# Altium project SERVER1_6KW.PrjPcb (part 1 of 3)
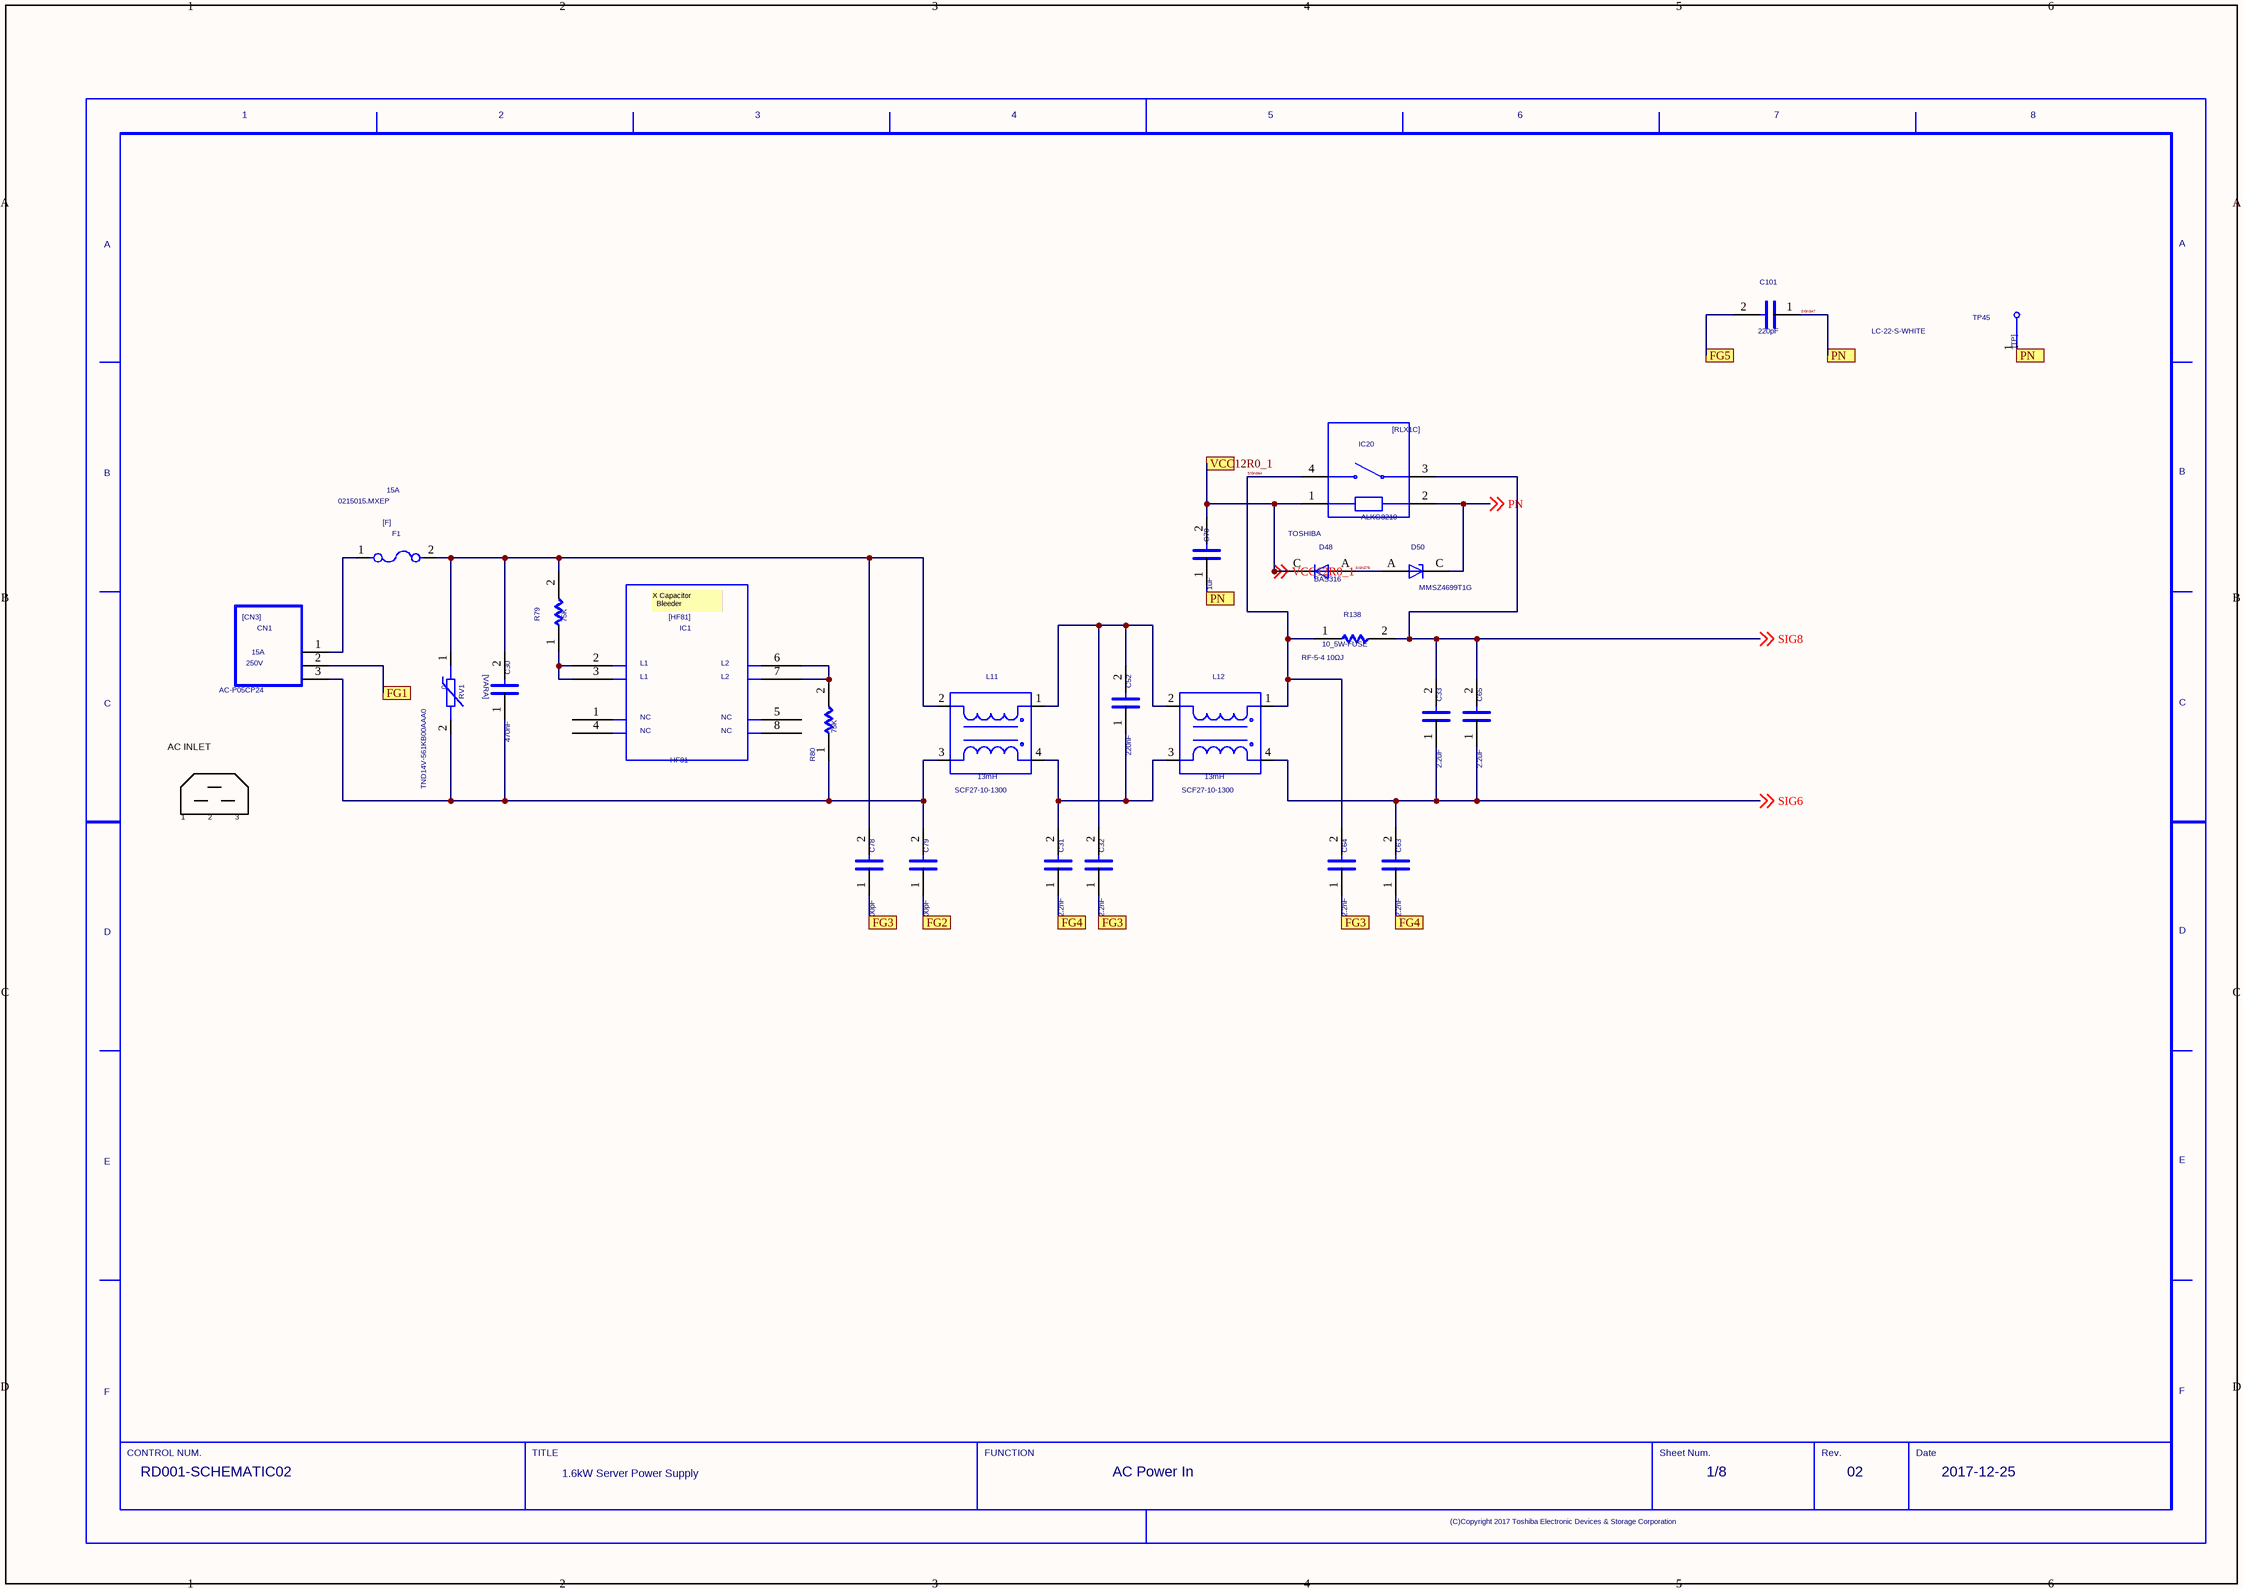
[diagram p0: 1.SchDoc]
8 sheets, 447 parts. Net scope: flat (ports and power ports of the same name join across sheets).
Sheets:
  1.SchDoc
  2.SchDoc
  3.SchDoc
  4.SchDoc
  5.SchDoc
  6.SchDoc
  7.SchDoc
  8.SchDoc

## Sheet 1.SchDoc
size 420 x 297 mm

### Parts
(Parts that share a designator on the sheet are numbered #1, #2 ... from top to bottom, then left to right.)
C30  VAL1: 470nF  (hidden comment: C)
C31  VAL1: 2.2nF  (hidden comment: C)
C32  VAL1: 2.2nF  (hidden comment: C)
C33  VAL1: 2.2uF  (hidden comment: C)
C52  VAL1: 220nF  (hidden comment: C)
C63  VAL1: 2.2nF  (hidden comment: C)
C64  VAL1: 2.2nF  (hidden comment: C)
C65  VAL1: 2.2uF  (hidden comment: C)
C70  VAL1: 1uF  (hidden comment: C)
C78  VAL1: 100pF  (hidden comment: C)
C79  VAL1: 100pF  (hidden comment: C)
C101  VAL1: 220pF  (hidden comment: C)
CN1  VAL2: 250V  VAL1: 15A  VAL3: AC-P05CP24  (hidden comment: CN3)
D48  USERCOMPTEXT3: TOSHIBA  VAL3: BAS316  (hidden comment: D)
D50  VAL3: MMSZ4699T1G  (hidden comment: ZD)
F1  VAL1: 15A  VAL3: 0215015.MXEP  (hidden comment: F)
IC1  VAL3: HF81  (hidden comment: L81)
IC20  VAL3: ALKG8210  (hidden comment: RLX1C)
L11  VAL3: SCF27-10-1300  VAL1: 13mH  (hidden comment: HM-DLWHN6702)
L12  VAL3: SCF27-10-1300  VAL1: 13mH  (hidden comment: HM-DLWHN6702)
R79  VAL1: 75K  (hidden comment: R)
R80  VAL1: 75K  (hidden comment: R)
R138  VAL3: RF-5-4 10ΩJ  VAL1: 10_5W-FUSE  (hidden comment: R)
RV1  VAL3: TND14V-561KB00AAA0  (hidden comment: VARA)
TP45  VAL3: LC-22-S-WHITE  (hidden comment: TP)
U?#1  DATE: 2017-12-25  TITLE: 1.6kW Server Power Supply  REVISION: 02  SHEETNUMBER: 1/8  DRAWINGNUMBER: RD001-SCHEMATIC02  FUNCTION: AC Power In  (hidden comment: WAKU_DEF100)

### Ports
FG1, FG2, FG3, FG4, FG5, PN, VCC12R0_1

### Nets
SIG1: C30.2 C78.2 F1.2 L11.2 R79.2 RV1.1
SIG2: C30.1 C79.2 CN1.3 L11.3 R80.1 RV1.2
SIG6: C33.1 C63.2 C65.1 L12.4 ; off-sheet SIG6
SIG8: C33.2 C65.2 IC20.3 R138.2 ; off-sheet SIG8
SIG9: IC1.2 IC1.3 R79.1
SIG10: IC1.6 IC1.7 R80.2
SIG193: CN1.1 F1.1
SIG199: C32.2 C52.2 L11.1 L12.2
SIG200: C31.2 C52.1 L11.4 L12.3
SIGN275: D48.A D50.A
SIGN347: C70.1 C101.1 D50.C IC20.2 TP45.1 ; off-sheet PN, port PN  [also labelled PN]
SIGN364: C64.2 IC20.4 L12.1 R138.1
VCC12R0_1: C70.2 D48.C IC20.1 ; off-sheet VCC12R0_1, port VCC12R0_1
NetC31_1: C31.1 C63.1 ; port FG4
NetC32_1: C32.1 C64.1 C78.1 ; port FG3
NetC79_1: C79.1 ; port FG2
NetC101_2: C101.2 ; port FG5
NetCN1_2: CN1.2 ; port FG1

Not connected (* = marked no-connect by the designer): IC1 1 4 5 8

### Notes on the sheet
- AC INLET
- 1
- 2
- 3

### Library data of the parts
C30 = C: OriginalSymbolOrigin: (2540,7620); COMP: PRT_19; MAKER: OKAYA; VAL2: 275V,±10%; VAL3: LE474-M; RATEDVOLTAGE: 100; MAXGCOUNT: 1; SIZECODESMD: 3225; NOMINALCAPACITA: 470n; CAPACITANCETOLE: K; ADSMODELNAME: s_GRM32MR72A474KA01L
C31 = C: OriginalSymbolOrigin: (2540,7620); PMPRODUCTSTYPEG: ES; COMP: PRT_13; VAL2: 250V,±20%; MAKER: MURATA; CHIPSIZE: リードピッチ7.5mm品希望; VAL3: DE2E3KY222MN3AM02F; RATEDVOLTAGE: 250; MAXGCOUNT: 1; TEMPCHARACTERI2: E; OUMEMAKER: NAE パナソニックエレクトロニックデバイス; QUADMODEL: CON_2.2N; FNLEADFREETHET1GT2GMCTH1: N_N_N; OUMECLASSIFICATION: セラミックコンデンサ; SIZECODESMD: DIP; NOMINALCAPACITA: 2.2n; OUMEMAKERKATAMEI: ECKNTS222ME; CAPACITANCETOLE: M; CDMASTERCADCELG: DC0284; ADSMODELNAME: s_ECKNTS222ME
C32 = C: SQ_PART_MODEL: CON_2.2N; OriginalSymbolOrigin: (2540,7620); PMPRODUCTSTYPEG: ES; COMP: PRT_13; VAL2: 250V,±20%; MAKER: MURATA; CHIPSIZE: リードピッチ7.5mm品希望; VAL3: DE2E3KY222MN3AM02F; RATEDVOLTAGE: 250; MAXGCOUNT: 1; TEMPCHARACTERI2: E; OUMEMAKER: NAE パナソニックエレクトロニックデバイス; FNLEADFREETHET1GT2GMCTH1: N_N_N; OUMECLASSIFICATION: セラミックコンデンサ; SIZECODESMD: DIP; NOMINALCAPACITA: 2.2n; ADSCNVFLAG: ON; OUMEMAKERKATAMEI: ECKNTS222ME; CAPACITANCETOLE: M; CDMASTERCADCELG: DC0284; ADSMODELNAME: s_ECKNTS222ME
C33 = C: OriginalSymbolOrigin: (2540,7620); FNLEADFREETHET1GT2GMCTH1: 9_N_N; CDMASTERCADCELG: DC0511; OUMEMAKER: CHM 日本ケミコン; OUMEMAKERKATAMEI: TACB2E225K; OUMECLASSIFICATION: フィルャRンデンサ; QUADMODEL: CON_2.2U; COMP: PRT_18; MAKER: Wurth; VAL2: 275V,±10%; VAL3: 890324026034CS; RATEDVOLTAGE: 250; MAXGCOUNT: 1; SIZECODESMD: DIP; NOMINALCAPACITA: 2.2u; CAPACITANCETOLE: K
C52 = C: OriginalSymbolOrigin: (2540,7620); FNLEADFREETHET1GT2GMCTH1: N_N_N; OUMEMAKER: NIS ニッセイ電機; OUMEMAKERKATAMEI: R40KI322000**M; OUMECLASSIFICATION: フィルャRンデンサ; QUADMODEL: CON_220N; COMP: PRT_17; MAKER: OKAYA; VAL2: 275V,±10%; VAL3: LE224-M; RATEDVOLTAGE: 275; MAXGCOUNT: 1; SIZECODESMD: DIP; NOMINALCAPACITA: 220n; CAPACITANCETOLE: M
C63 C64 = C: OriginalSymbolOrigin: (2540,7620); PMPRODUCTSTYPEG: PC1; COMP: PRT_13; VAL2: 250V,±20%; MAKER: MURATA; CHIPSIZE: リードピッチ7.5mm品希望; VAL3: DE2E3KY222MN3AM02F; TEMPCHARACTERI2: E; RATEDVOLTAGE: 250; MAXGCOUNT: 1; OUMEMAKER: MRT 村田製作所; QUADMODEL: CON_2.2N; FNLEADFREETHET1GT2GMCTH1: N_N_N; OUMECLASSIFICATION: セラミックコンデンサ; SIZECODESMD: DIP; NOMINALCAPACITA: 2.2n; CAPACITANCETOLE: M; CDMASTERCADCELG: SIK0018; ADSMODELNAME: s_DE2E3KY222MN3AM02F
C65 = C: OriginalSymbolOrigin: (2540,7620); FNLEADFREETHET1GT2GMCTH1: 9_N_N; CDMASTERCADCELG: DC0511; OUMEMAKER: CHM 日本ケミコン; OUMEMAKERKATAMEI: TACB2E225K; OUMECLASSIFICATION: フィルャRンデンサ; QUADMODEL: CON_2.2U; COMP: PRT_18; MAKER: Wurth; VAL2: 270V,±10%; VAL3: 890324026034CS; RATEDVOLTAGE: 250; MAXGCOUNT: 1; SIZECODESMD: DIP; NOMINALCAPACITA: 2.2u; CAPACITANCETOLE: K
C70 = C: OriginalSymbolOrigin: (2540,7620); COMP: PRT_52; VAL3: C1005X5R1E105M050BC; MAKER: TDK; CHIPSIZE: 1005; VAL2: 25V,±20%; TEMPCHARACTERI2: B; PMPRODUCTSTYPEG: HD1; RATEDVOLTAGE: 25; MAXGCOUNT: 1; OUMEMAKER: MRT 村田製作所; QUADMODEL: CON_1U; FNLEADFREETHET1GT2GMCTH1: 3_0_N; OUMECLASSIFICATION: セラミックコンデンサ; NOMINALCAPACITA: 1u; OUMEMAKERKATAMEI: GRM155B31E105KA12D; CAPACITANCETOLE: K; CDMASTERCADCELG: KC0005; ADSMODELNAME: s_GRM155B31E105KA12D
C78 C79 = C: OriginalSymbolOrigin: (2540,7620); FNLEADFREETHET1GT2GMCTH1: N_N_N; CDMASTERCADCELG: RDK0051; OUMEMAKER: MRT 村田製作所; OUMEMAKERKATAMEI: DE1B3KX101KA4BL01; OUMECLASSIFICATION: セラミックコンデンサ; QUADMODEL: CON_100P; COMP: PRT_29; VAL2: 250V,±10%; MAKER: MURATA; VAL3: DE2B3KY101KA3BM02F; CHIPSIZE: リードピッチ7.5mm品希望; RATEDVOLTAGE: 250; MAXGCOUNT: 1; TEMPCHARACTERI2: B; NOMINALCAPACITA: 100p; CAPACITANCETOLE: K; ADSMODELNAME: s_DE1B3KX101KA4BL01
C101 = C: OriginalSymbolOrigin: (2540,7620); FNLEADFREETHET1GT2GMCTH1: 9_1_N; CDMASTERCADCELG: RD0002; OUMEMAKER: MRT 村田製作所; OUMEMAKERKATAMEI: DEBB33A221KC1B; OUMECLASSIFICATION: セラミックコンデンサ; QUADMODEL: CON_220P; VAL2: 250V,±10%; COMP: PRT_50; MAKER: MURATA; VAL3: DE2B3KY221KA3BM02F; TEMPCHARACTERI2: B; RATEDVOLTAGE: 1K; MAXGCOUNT: 1; SIZECODESMD: DIP; NOMINALCAPACITA: 220p; CAPACITANCETOLE: K; ADSMODELNAME: s_DEBB33A221KC1B
CN1 = CN3: OriginalSymbolOrigin: (2540,17780); MAKER: ECHO ELECTRIC; COMP: PRT_61
D48 = D: SAVEAREA0: -225,-91,12804,7836; SAVECOUNT: 3; TIME: 14:49:55; UPDATEUSER: 19870035; UPDATETIME: 14:20:16; OriginalSymbolOrigin: (5080,5080); COMP: PRT_26; FORWARDVOLTAGEM: 0; MAXGCOUNT: 1; OUMEMAKER: IFO インフィニオンテクノロジーズ; MOUNTINGFORMSMD: SMD; FNLEADFREETHET1GT2GMCTH1: N_N_N; OUMECLASSIFICATION: その他ダイオード; OUMEMAKERKATAMEI: BAS16-02W; CDMASTERCADCELG: D8101D; ADSMODELNAME: s_BAS16_02W
D50 = ZD: OUMEPARTTYPE: D; SAVEAREA0: -4630,-153,17114,13055; TIME: 14:49:55; UPDATEUSER: fukuda-y; UPDATETIME: 08:18:42; SAVECOUNT: 6; OriginalSymbolOrigin: (5080,5080); COMP: PRT_47; MAKER: ON Semiconductor; FORWARDVOLTAGEM: 0; MAXGCOUNT: 1; OUMEMAKER: ONS オンセミコンダクター; MOUNTINGFORMSMD: SMD; FNLEADFREETHET1GT2GMCTH1: N_N_N; ZENERVOLTAGEMIN: 2.28; OUMECLASSIFICATION: 定電圧ダイオード; OUMEMAKERKATAMEI: MMSZ4681T1G; CDMASTERCADCELG: MMK0127; ZENERVOLTAGEMAX: 2.52; ADSMODELNAME: s_MMSZ4681T1G
F1 = F: OriginalSymbolOrigin: (2540,5080); COMP: PRT_21; MAKER: Littelfuse; RATEDVOLTAGE: 0; MAXGCOUNT: 1; MOUNTINGFORMSMD: SMD
IC1 = L81: SAVEAREA0: -12429,-3512,55842,41521; TIME: 18:31:00; UPDATEUSER: cae; UPDATETIME: 11:10:50; SAVECOUNT: 13; OriginalSymbolOrigin: (7620,35560); MAKER: MPS; COMP: PRT_45
IC20 = RLX1C: SAVECOUNT: 9; SAVEAREA0: -15461,-296,40419,28727; OriginalSymbolOrigin: (5080,20320); COMP: PRT_1; MAKER: PANASONIC; UPDATETIME: 11:13:08; UPDATEUSER: cae; TIME: 14:49:55
L11 L12 = HM-DLWHN6702: DEVICENAME: DLW21HN670SQ2; SAVEAREA0: -21350,-26515,41553,39372; TIME: 11:39:40; UPDATEUSER: user1; UPDATETIME: 19:05:24; SAVECOUNT: 4; OriginalSymbolOrigin: (2540,12700); MAKER: NEC TOKIN; COMP: PRT_22
R79 R80 = R: OriginalSymbolOrigin: (5080,5080); POWERRATING: 250m; RESISTANCETOLER: F; NOMINALRESISTAN: 56K; FNLEADFREETHET1GT2GMCTH1: N_N_N; CDMASTERCADCELG: DR903A; OUMEMAKER: KOA コーア; OUMEMAKERKATAMEI: RK73H2ETE563F; OUMECLASSIFICATION: 表面実装用固定抵抗器; QUADMODEL: RES_56K; COMP: PRT_23; MAKER: PANASONIC; VAL3: ERJ-14NF7502U; CHIPSIZE: 3225; VAL2: 500mW,±1%; MAXGCOUNT: 1; MOUNTINGFORMSMD: SMD; ADSMODELNAME: s_RK73H2ETE563F
R138 = R: OriginalSymbolOrigin: (5080,5080); MAKER: TAKMAN; CHIPSIZE: 13x9xH25.5; COMP: PRT_33
RV1 = VARA: OUMEPARTTYPE: RV; SAVEAREA0: -9950,-8554,25168,13619; SAVECOUNT: 12; TIME: 09:56:50; UPDATEUSER: tomizawa-y; OriginalSymbolOrigin: (2540,5080); COMP: PRT_37; MAKER: NIPPON CHEMICON; VAL1: 560V; RATEDVOLTAGE: 0; MAXGCOUNT: 1; OUMEMAKER: TDK ＴＤＫ; MOUNTINGFORMSMD: SMD; FNLEADFREETHET1GT2GMCTH1: N_N_N; OUMECLASSIFICATION: バリスタ; OUMEMAKERKATAMEI: AVR-M1608C220KT6AB; CDMASTERCADCELG: KC0008
TP45 = TP: TIME: 16:12:21; UPDATEUSER: fukuda-y; UPDATETIME: 16:18:11; SAVECOUNT: 2; SAVEAREA0: -242,-92,12810,7836; OriginalSymbolOrigin: (0,7620); COMP: PRT_49; MAKER: MAC8
U?#1 = WAKU_DEF100: PLOTTIME: HH:MM; SAVEAREA0: -45080,-4508,463680,304612; TIME: 10:19:22; UPDATEUSER: f1043010; UPDATETIME: 13:49:58; SAVECOUNT: 3; OriginalSymbolOrigin: (10160,284480); PAGENUMBER: 2; DESIGNED: TOSHIBA

## Sheet 2.SchDoc
size 420 x 297 mm
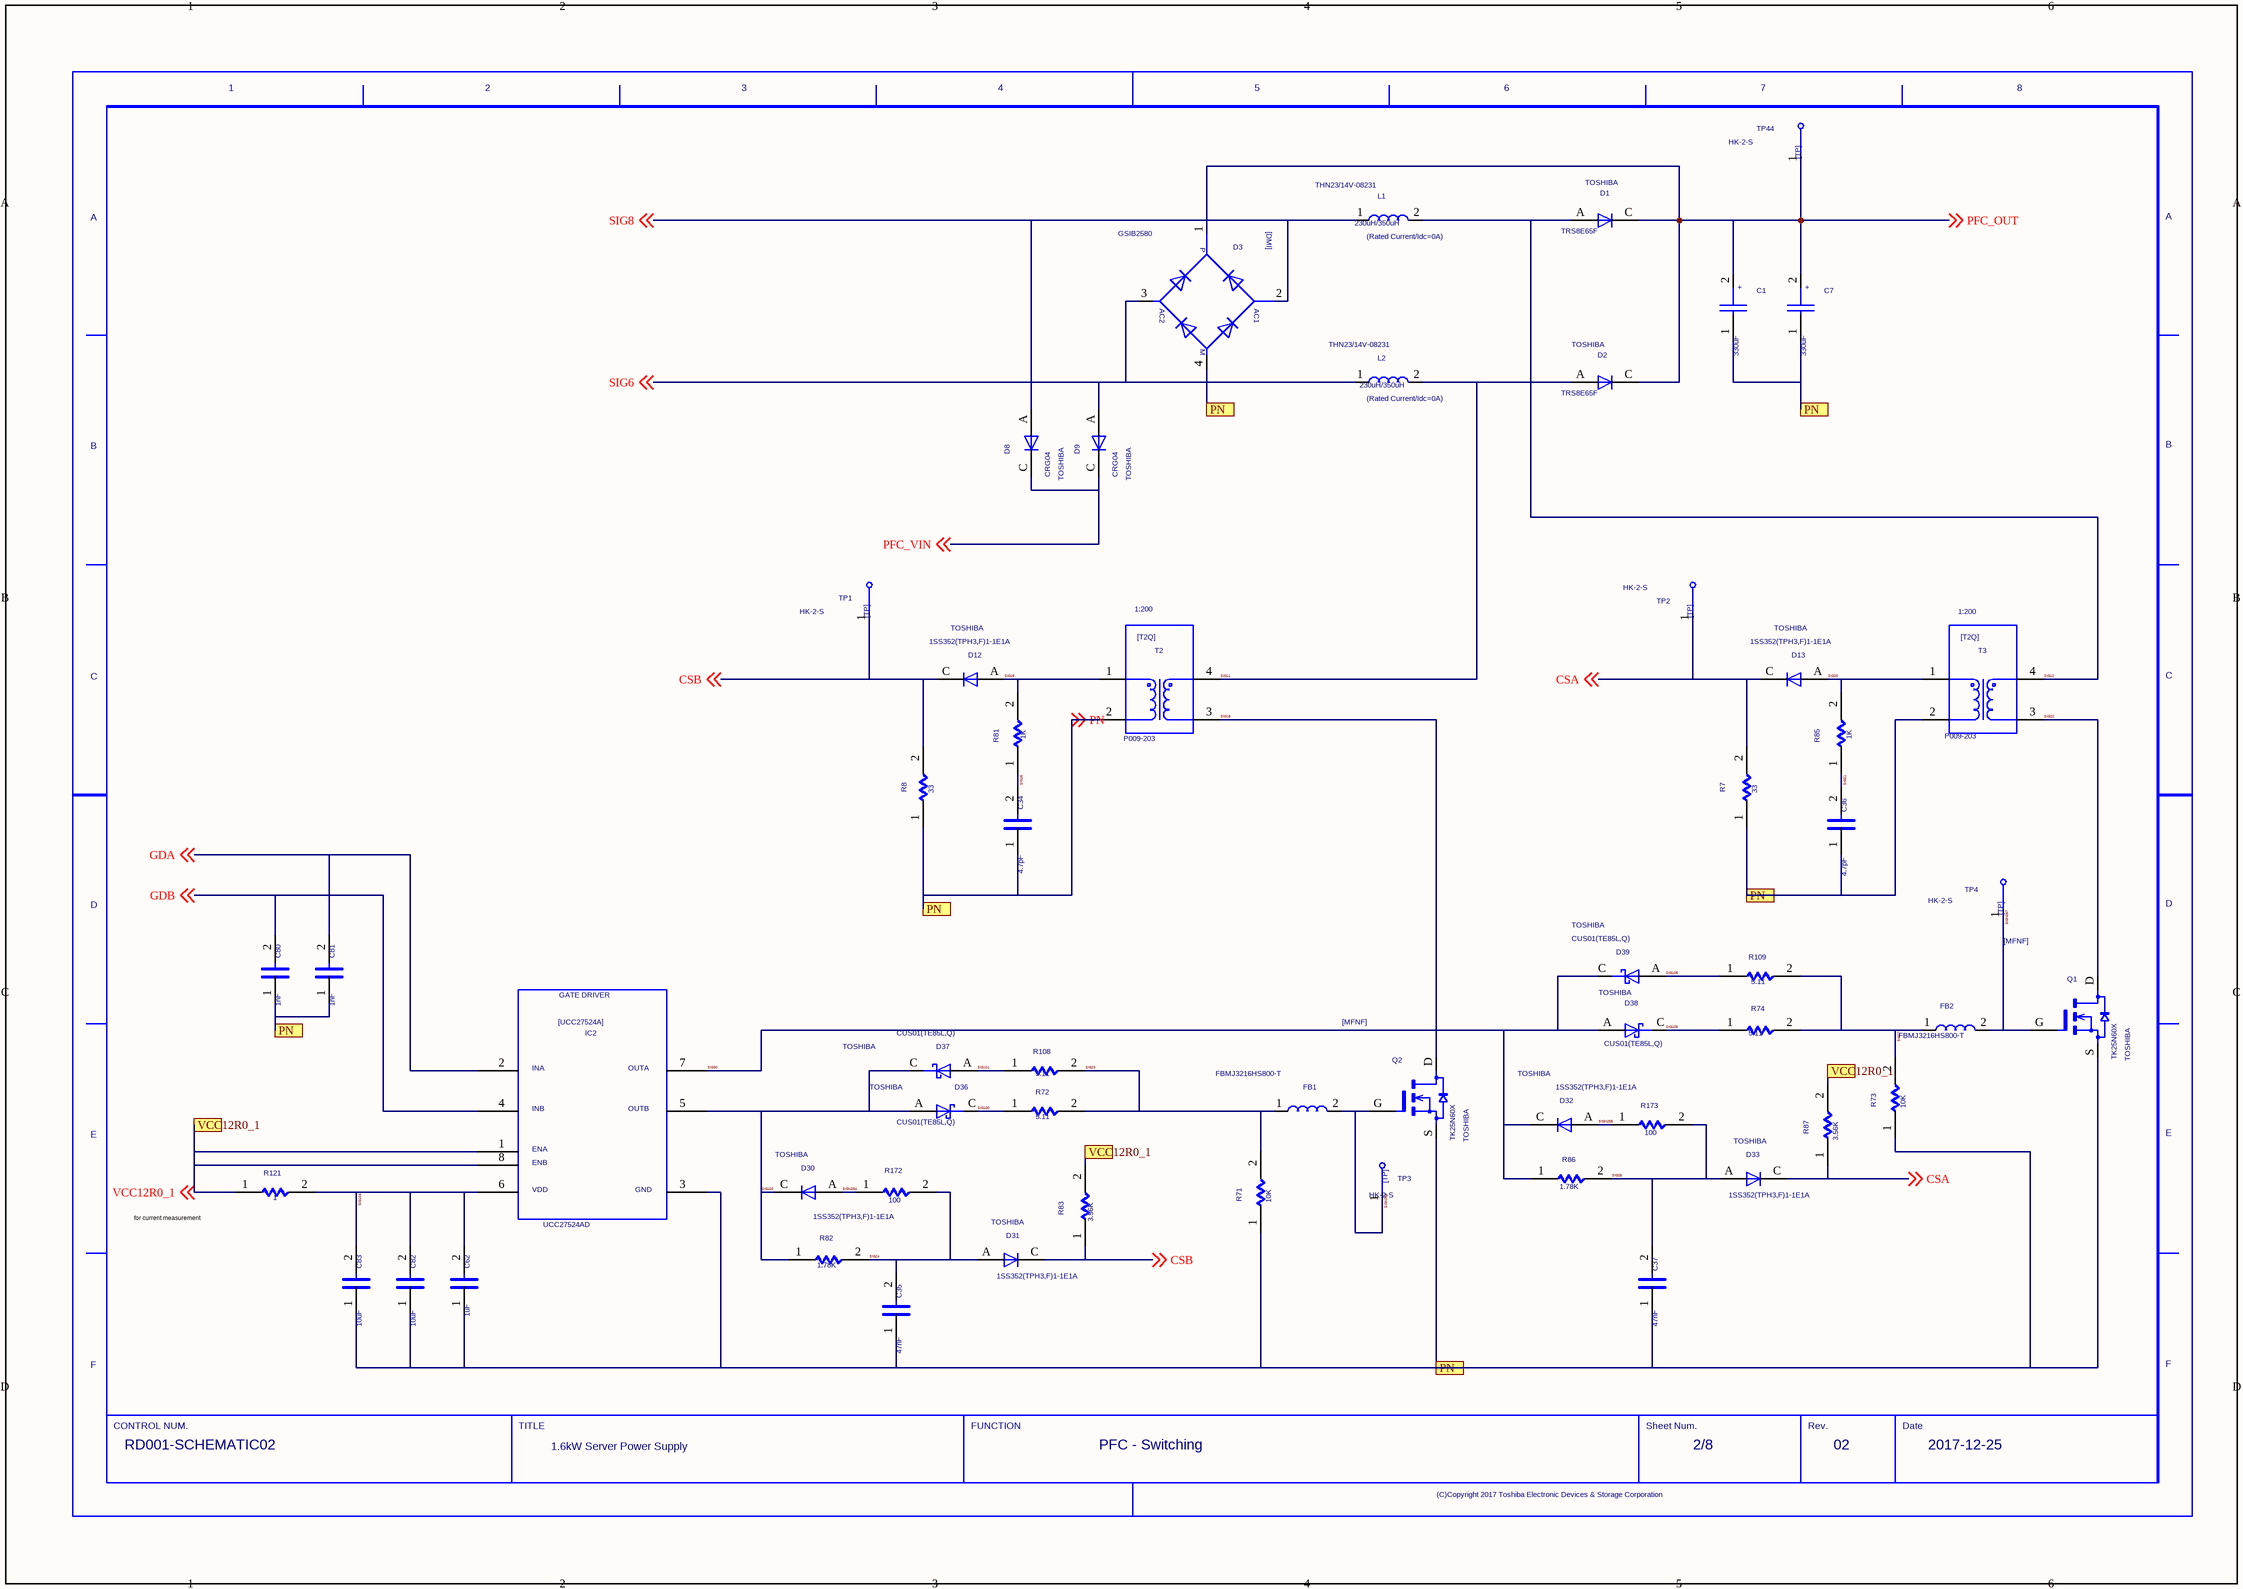
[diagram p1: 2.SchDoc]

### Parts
(Parts that share a designator on the sheet are numbered #1, #2 ... from top to bottom, then left to right.)
C1  VAL1: 330uF  (hidden comment: CP)
C7  VAL1: 330uF  (hidden comment: CP)
C34  VAL1: 4.7pF  (hidden comment: C)
C35  VAL1: 47nF  (hidden comment: C)
C36  VAL1: 4.7pF  (hidden comment: C)
C37  VAL1: 47nF  (hidden comment: C)
C62  VAL1: 1uF  (hidden comment: C)
C80  VAL1: 1nF  (hidden comment: C)
C81  VAL1: 1nF  (hidden comment: C)
C82  VAL1: 10uF  (hidden comment: C)
C83  VAL1: 10uF  (hidden comment: C)
D1  USERCOMPTEXT3: TOSHIBA  VAL3: TRS8E65F  (hidden comment: D)
D2  USERCOMPTEXT3: TOSHIBA  VAL3: TRS8E65F  (hidden comment: D)
D3  VAL3: GSIB2580  (hidden comment: DMI)
D8  USERCOMPTEXT3: TOSHIBA  VAL3: CRG04  (hidden comment: D)
D9  USERCOMPTEXT3: TOSHIBA  VAL3: CRG04  (hidden comment: D)
D12  USERCOMPTEXT3: TOSHIBA  VAL1: 1SS352(TPH3,F)1-1E1A  (hidden comment: D)
D13  USERCOMPTEXT3: TOSHIBA  VAL1: 1SS352(TPH3,F)1-1E1A  (hidden comment: D)
D30  USERCOMPTEXT3: TOSHIBA  VAL1: 1SS352(TPH3,F)1-1E1A  (hidden comment: D)
D31  USERCOMPTEXT3: TOSHIBA  VAL1: 1SS352(TPH3,F)1-1E1A  (hidden comment: D)
D32  USERCOMPTEXT3: TOSHIBA  VAL1: 1SS352(TPH3,F)1-1E1A  (hidden comment: D)
D33  USERCOMPTEXT3: TOSHIBA  VAL1: 1SS352(TPH3,F)1-1E1A  (hidden comment: D)
D36  USERCOMPTEXT3: TOSHIBA  VAL1: CUS01(TE85L,Q)  (hidden comment: SBD)
D37  USERCOMPTEXT3: TOSHIBA  VAL1: CUS01(TE85L,Q)  (hidden comment: SBD)
D38  USERCOMPTEXT3: TOSHIBA  VAL1: CUS01(TE85L,Q)  (hidden comment: SBD)
D39  USERCOMPTEXT3: TOSHIBA  VAL1: CUS01(TE85L,Q)  (hidden comment: SBD)
FB1  VAL3: FBMJ3216HS800-T  (hidden comment: L)
FB2  VAL3: FBMJ3216HS800-T  (hidden comment: L)
IC2  VAL3: UCC27524AD  (hidden comment: L27524)
L1  VAL2: (Rated Current/Idc=0A)  VAL1: 230uH/350uH  VAL3: THN23/14V-08231  (hidden comment: L)
L2  VAL2: (Rated Current/Idc=0A)  VAL1: 230uH/350uH  VAL3: THN23/14V-08231  (hidden comment: L)
Q1  USERCOMPTEXT3: TOSHIBA  VAL3: TK25N60X  (hidden comment: MFNF)
Q2  USERCOMPTEXT3: TOSHIBA  VAL3: TK25N60X  (hidden comment: MFNF)
R7  VAL1: 33  (hidden comment: R)
R8  VAL1: 33  (hidden comment: R)
R71  VAL1: 10K  (hidden comment: R)
R72  VAL1: 5.11  (hidden comment: R)
R73  VAL1: 10K  (hidden comment: R)
R74  VAL1: 5.11  (hidden comment: R)
R81  VAL1: 1K  (hidden comment: R)
R82  VAL1: 1.78K  (hidden comment: R)
R83  VAL1: 3.56K  (hidden comment: R)
R85  VAL1: 1K  (hidden comment: R)
R86  VAL1: 1.78K  (hidden comment: R)
R87  VAL1: 3.56K  (hidden comment: R)
R108  VAL1: 5.11  (hidden comment: R)
R109  VAL1: 5.11  (hidden comment: R)
R121  VAL1: 1  (hidden comment: R)
R172  VAL1: 100  (hidden comment: R)
R173  VAL1: 100  (hidden comment: R)
T2  VAL1: 1:200  VAL3: P009-203  (hidden comment: T2Q)
T3  VAL1: 1:200  VAL3: P009-203  (hidden comment: T2Q)
TP1  VAL3: HK-2-S  (hidden comment: TP)
TP2  VAL3: HK-2-S  (hidden comment: TP)
TP3  VAL3: HK-2-S  (hidden comment: TP)
TP4  VAL3: HK-2-S  (hidden comment: TP)
TP44  VAL3: HK-2-S  (hidden comment: TP)
U?#2  DATE: 2017-12-25  TITLE: 1.6kW Server Power Supply  REVISION: 02  SHEETNUMBER: 2/8  DRAWINGNUMBER: RD001-SCHEMATIC02  FUNCTION: PFC - Switching  (hidden comment: WAKU_DEF100)

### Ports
PN, VCC12R0_1

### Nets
CSA: D13.C D33.C R7.2 R87.1 TP2.1 ; off-sheet CSA
CSB: D12.C D31.C R8.2 R83.1 TP1.1 ; off-sheet CSB
GDA: C81.2 IC2.2 ; off-sheet GDA
GDB: C80.2 IC2.4 ; off-sheet GDB
PFC_OUT: C1.2 C7.2 D1.C D2.C D3.1 TP44.1 ; off-sheet PFC_OUT
PFC_VIN: D8.C D9.C ; off-sheet PFC_VIN
PN: C1.1 C7.1 C34.1 C35.1 C36.1 C37.1 C62.1 C80.1 C81.1 C82.1 C83.1 D3.4 IC2.3 Q1.S Q2.S R7.1 R8.1 R71.1 R73.1 T2.2 T3.2 ; off-sheet PN, port PN  [project net SIGN347]
SIG6: D3.3 D9.A L2.1 ; off-sheet SIG6
SIG8: D3.2 D8.A L1.1 ; off-sheet SIG8
SIG11: D2.A L2.2 T2.4
SIG12: D1.A L1.2 T3.4
SIG15: D12.A R81.2 T2.1
SIG16: C34.2 R81.1
SIG18: Q2.D T2.3
SIG20: D13.A R85.2 T3.1
SIG21: C36.2 R85.1
SIG22: Q1.D T3.3
SIG23: FB1.1 R71.2 R72.2 R108.2
SIG24: C35.2 D31.A R82.2 R172.2
SIG25: C37.2 D33.A R86.2 R173.2
SIG27: FB2.1 R73.2 R74.2 R109.2
SIG30: D32.C D38.A D39.C IC2.7 R86.1
SIG100: D36.C R72.1
SIG101: D37.A R108.1
SIG102: D30.C D36.A D37.C IC2.5 R82.1
SIG104: C62.2 C82.2 C83.2 IC2.6 R121.2
SIG105: D39.A R109.1
SIG106: D38.C R74.1
SIGN254: D30.A R172.1
SIGN255: D32.A R173.1
SIGN266: FB1.2 Q2.G TP3.1
SIGN267: FB2.2 Q1.G TP4.1
VCC12R0_1: IC2.1 IC2.8 R83.2 R87.2 R121.1 ; off-sheet VCC12R0_1, port VCC12R0_1

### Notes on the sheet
- for current measurement

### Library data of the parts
C1 = CP: OUMEPARTTYPE: C; SAVEAREA0: -1450,-153,20294,13055; SAVECOUNT: 52; TIME: 15:02:55; UPDATEUSER: fukuda-y; UPDATETIME: 16:13:42; OriginalSymbolOrigin: (2540,10160); FNLEADFREETHET1GT2GMCTH1: 9_N_N; CDMASTERCADCELG: DC213N; OUMEMAKER: SIT ルビコン; OUMEMAKERKATAMEI: 450MXC330M35X40; OUMECLASSIFICATION: アルミ電解コンデンサ; QUADMODEL: CON_330U; COMP: PRT_4; MAKER: RUBYCON; CHIPSIZE: D35xL30; VAL2: 450V; RATEDVOLTAGE: 450; MAXGCOUNT: 1; SIZECODESMD: DIP; NOMINALCAPACITA: 330u; VAL3: 450MXH330; CAPACITANCETOLE: M
C7 = CP: OUMEPARTTYPE: C; SAVEAREA0: -1450,-153,20294,13055; SAVECOUNT: 52; TIME: 15:02:55; UPDATEUSER: fukuda-y; UPDATETIME: 16:13:42; OriginalSymbolOrigin: (2540,10160); FNLEADFREETHET1GT2GMCTH1: 9_N_N; CDMASTERCADCELG: DC213N; OUMEMAKER: SIT ルビコン; OUMEMAKERKATAMEI: 450MXC330M35X40; OUMECLASSIFICATION: アルミ電解コンデンサ; QUADMODEL: CON_330U; COMP: PRT_4; MAKER: RUBYCON; CHIPSIZE: D35xL30; VAL2: 450V,±20%; RATEDVOLTAGE: 450; MAXGCOUNT: 1; SIZECODESMD: DIP; NOMINALCAPACITA: 330u; VAL3: 450MXH330; CAPACITANCETOLE: M
C34 C36 = C: OriginalSymbolOrigin: (2540,7620); COMP: PRT_52; VAL3: GRM1555C1H4R7BA01D; MAKER: MURATA; CHIPSIZE: 1005; VAL2: 50V,±0.1pF; PMPRODUCTSTYPEG: DME; RATEDVOLTAGE: 50; MAXGCOUNT: 1; TEMPCHARACTERI2: CH; OUMEMAKER: MRT 村田製作所; QUADMODEL: CON_4.7P; FNLEADFREETHET1GT2GMCTH1: N_N_N; OUMECLASSIFICATION: セラミックコンデンサ; NOMINALCAPACITA: 4.7p; OUMEMAKERKATAMEI: GRM1552C1H4R7CA01D; CDMASTERCADCELG: KC0005; ADSMODELNAME: s_GRM1552C1H4R7CA01D
C35 = C: SQ_PART_MODEL: CON_47N; OriginalSymbolOrigin: (2540,7620); COMP: PRT_52; VAL3: GRM155R71E473KA88D; MAKER: MURATA; CHIPSIZE: 1005; VAL2: 25V,±10%; TEMPCHARACTERI2: R; RATEDVOLTAGE: 16; MAXGCOUNT: 1; OUMEMAKER: MRT 村田製作所; FNLEADFREETHET1GT2GMCTH1: N_N_N; OUMECLASSIFICATION: セラミックコンデンサ; NOMINALCAPACITA: 47n; ADSCNVFLAG: ON; OUMEMAKERKATAMEI: GCM155R11C473KA01J; ADSCOMPONENTNAME: C_1005; CAPACITANCETOLE: K; CDMASTERCADCELG: KC0005; ADSMODELNAME: s_GCM155R11C473KA01J
C37 = C: OriginalSymbolOrigin: (2540,7620); COMP: PRT_52; VAL3: GRM155R71E473KA88D; MAKER: MURATA; CHIPSIZE: 1005; VAL2: 25V,±10%; TEMPCHARACTERI2: R; RATEDVOLTAGE: 16; MAXGCOUNT: 1; OUMEMAKER: MRT 村田製作所; QUADMODEL: CON_47N; FNLEADFREETHET1GT2GMCTH1: N_N_N; OUMECLASSIFICATION: セラミックコンデンサ; NOMINALCAPACITA: 47n; OUMEMAKERKATAMEI: GCM155R11C473KA01J; CAPACITANCETOLE: K; CDMASTERCADCELG: KC0005; ADSMODELNAME: s_GCM155R11C473KA01J
C62 = C: OriginalSymbolOrigin: (2540,7620); COMP: PRT_52; VAL3: C1005X5R1E105M050BC; MAKER: TDK; CHIPSIZE: 1005; VAL2: 25V,±20%; RATEDVOLTAGE: 16; MAXGCOUNT: 1; OUMEMAKER: TDK ＴＤＫ; QUADMODEL: CON_1U; FNLEADFREETHET1GT2GMCTH1: N_N_N; OUMECLASSIFICATION: セラミックコンデンサ; NOMINALCAPACITA: 1u; OUMEMAKERKATAMEI: C1005X5R1C105M050BC; CAPACITANCETOLE: M; CDMASTERCADCELG: KC0005; ADSMODELNAME: s_C1005X5R1C105M050BC
C80 C81 = C: OriginalSymbolOrigin: (2540,7620); COMP: PRT_52; PMPRODUCTSTYPEG: HD1-PC1; FNLEADFREETHET1GT2GMCTH1: 2_0_N; CDMASTERCADCELG: KC0005; OUMEMAKER: TYD 太陽誘電; OUMEMAKERKATAMEI: UMK105BJ102KV-F; OUMECLASSIFICATION: セラミックコンデンサ; QUADMODEL: CON_1N; MAKER: TDK; CHIPSIZE: 1005; VAL2: 50V,±10%; RATEDVOLTAGE: 50; MAXGCOUNT: 1; TEMPCHARACTERI2: B; NOMINALCAPACITA: 1n; CAPACITANCETOLE: K; ADSMODELNAME: s_UMK105BJ102KV_F
C82 C83 = C: OriginalSymbolOrigin: (2540,7620); FNLEADFREETHET1GT2GMCTH1: N_N_N; CDMASTERCADCELG: KC0014; OUMEMAKER: TYD 太陽誘電; OUMEMAKERKATAMEI: TMK316LD106KL-T; OUMECLASSIFICATION: セラミックコンデンサ; QUADMODEL: CON_10U; COMP: PRT_46; MAKER: TAIYO YUDEN; CHIPSIZE: 3216; VAL3: TMK316BJ106KL-T; VAL2: 25V,±10%; RATEDVOLTAGE: 25; MAXGCOUNT: 1; NOMINALCAPACITA: 10u; CAPACITANCETOLE: K; ADSMODELNAME: s_TMK316LD106KL_T
D1 D2 = D: SAVEAREA0: -225,-91,12804,7836; SAVECOUNT: 3; TIME: 14:49:55; UPDATEUSER: 19870035; UPDATETIME: 14:20:16; OriginalSymbolOrigin: (5080,5080); COMP: PRT_12; FORWARDVOLTAGEM: 0; MAXREVERSEVOLTA: 100; MAXGCOUNT: 1; OUMEMAKER: ROH ロー・; MOUNTINGFORMSMD: DIP; FNLEADFREETHET1GT2GMCTH1: N_N_N; OUMECLASSIFICATION: 小信号ダイオード; OUMEMAKERKATAMEI: 1N4148; CDMASTERCADCELG: DCR071; ADSMODELNAME: s_1N4148
D3 = DMI: OUMEPARTTYPE: D; SAVECOUNT: 7; SAVEAREA0: -7762,-358,32649,26224; TIME: 10:09:47; UPDATEUSER: fukuda-y; UPDATETIME: 17:30:39; OriginalSymbolOrigin: (0,25400); COMP: PRT_53; MAKER: VISHAY; FORWARDVOLTAGEM: 0; MAXGCOUNT: 1; MAXREPETITIVEPE: 800; OUMEMAKER: SDG 新電元工業; MAXAVERAGEFORWA: 800m; PEAKFORWARDVOLT: 950m; MOUNTINGFORMSMD: SMD; REVERSECURRENT: 10u; FNLEADFREETHET1GT2GMCTH1: N_N_N; OUMECLASSIFICATION: 一般整流素子; OUMEMAKERKATAMEI: D1UBA80_EMBEDED; CDMASTERCADCELG: MMK0161; ADSMODELNAME: s_D1UBA80_EMBEDED
D8 D9 = D: SAVEAREA0: -225,-91,12804,7836; SAVECOUNT: 3; TIME: 14:49:55; UPDATEUSER: 19870035; UPDATETIME: 14:20:16; OriginalSymbolOrigin: (5080,5080); COMP: PRT_24; PMPRODUCTSTYPEG: HD1; FORWARDVOLTAGEM: 0; MAXGCOUNT: 1; MAXREPETITIVEPE: 400; OUMEMAKER: TSB 東芝; PEAKFORWARDVOLT: 1.1; MOUNTINGFORMSMD: SMD; REVERSECURRENT: 10u; FNLEADFREETHET1GT2GMCTH1: N_N_N; OUMECLASSIFICATION: 一般整流素子; OUMEMAKERKATAMEI: CRG03(T5L,TEMQ); CDMASTERCADCELG: MMK0167; ADSMODELNAME: s_CRG03_T5L_TEMQ_
D12 D13 D30 D32 D33 = D: SAVEAREA0: -225,-91,12804,7836; SAVECOUNT: 3; TIME: 14:49:55; UPDATEUSER: 19870035; UPDATETIME: 14:20:16; OriginalSymbolOrigin: (5080,5080); COMP: PRT_27; FORWARDVOLTAGEM: 0; MAXREVERSEVOLTA: 80; MAXGCOUNT: 1; OUMEMAKER: TSB 東芝; MOUNTINGFORMSMD: SMD; FNLEADFREETHET1GT2GMCTH1: N_N_N; OUMECLASSIFICATION: 小信号ダイオード; CDMASTERCADCELG: D81022; ADSMODELNAME: s_1SS352_TPH3_F_1_1E1A
D31 = D: SAVEAREA0: -225,-91,12804,7836; SAVECOUNT: 3; TIME: 14:49:55; UPDATEUSER: 19870035; UPDATETIME: 14:20:16; OriginalSymbolOrigin: (5080,5080); COMP: PRT_27; FORWARDVOLTAGEM: 0; MAXREVERSEVOLTA: 80; MAXGCOUNT: 1; OUMEMAKER: TSB 東芝; MOUNTINGFORMSMD: SMD; FNLEADFREETHET1GT2GMCTH1: N_N_N; OUMECLASSIFICATION: 小信号ダイオード; ADSCNVFLAG: ON; ADSCOMPONENTNAME: D_D; CDMASTERCADCELG: D81022; ADSMODELNAME: s_1SS352_TPH3_F_1_1E1A
D36-D39 = SBD: OUMEPARTTYPE: D; SAVEAREA0: -4630,-153,17114,13055; TIME: 14:49:55; UPDATEUSER: fukuda-y; UPDATETIME: 08:16:22; SAVECOUNT: 9; OriginalSymbolOrigin: (5080,5080); COMP: PRT_11; FORWARDVOLTAGEM: 0; MAXGCOUNT: 1; MAXREPETITIVEPE: 30; OUMEMAKER: TSB 東芝; PEAKFORWARDVOLT: 370m; MOUNTINGFORMSMD: SMD; REVERSECURRENT: 500u; FNLEADFREETHET1GT2GMCTH1: 2_0_N; OUMECLASSIFICATION: 高速用整流素子/ショットキバリアダイオード; PMPRODUCTSTYPEG: PC1; CDMASTERCADCELG: MM0042; ADSMODELNAME: s_CUS01_TE85L_Q_
FB1 FB2 = L: OriginalSymbolOrigin: (2540,5080); COMP: PRT_30; MAKER: TAIYO YUDEN
IC2 = L27524: SAVEAREA0: -24347,-591,50370,48694; SAVECOUNT: 22; TIME: 15:02:55; UPDATEUSER: cae; UPDATETIME: 14:54:38; OriginalSymbolOrigin: (7620,45720); MAKER: TEXAS; COMP: PRT_63
L1 L2 = L: OriginalSymbolOrigin: (2540,5080); COMP: PRT_41; MAKER: TMP; INDUCTANCEMAX: 0; MAXGCOUNT: 1; MOUNTINGFORMSMD: DIP; NOMINALINDUCTA2: K; NOMINALINDUCTA1: 100u
Q1 Q2 = MFNF: SAVECOUNT: 11; SAVEAREA0: -7027,-292,21786,15988; OriginalSymbolOrigin: (5080,12700); COMP: PRT_31
R7 R8 = R: OriginalSymbolOrigin: (5080,5080); COMP: PRT_23; MAKER: PANASONIC; VAL3: ERJ-14YJ330U; CHIPSIZE: 3225; VAL2: 500mW,±5%
R71 R73 = R: OriginalSymbolOrigin: (5080,5080); COMP: PRT_8; VAL3: RK73B1JTTD103J; MAKER: KOA; CHIPSIZE: 1608; VAL2: 100mW,±5%; MAXGCOUNT: 1; OUMEMAKER: KOA コーア; QUADMODEL: RES_10K; MOUNTINGFORMSMD: SMD; FNLEADFREETHET1GT2GMCTH1: N_N_N; OUMECLASSIFICATION: 表面実装用固定抵抗器; RESISTANCETOLER: J; POWERRATING: 100m; OUMEMAKERKATAMEI: RK73B1JTTD103J@@; CDMASTERCADCELG: KC0133; ADSMODELNAME: s_RK73B1JTTD103J@@
R72 R74 R108 R109 = R: OriginalSymbolOrigin: (5080,5080); COMP: PRT_5; VAL3: CRM1206-FX-5R11ELF; MAKER: BOURNS; CHIPSIZE: 3216; MOUNTINGFORMSMD: SMD; OUMEMAKER: KOA コーア; OUMEMAKERKATAMEI: RK73H2BTTD6R80F; ADSMODELNAME: s_RK73H2BTTD6R80F; MAXGCOUNT: 1; QUADMODEL: RES_6.8; FNLEADFREETHET1GT2GMCTH1: 3_1_N; OUMECLASSIFICATION: 表面実装用固定抵抗器; RESISTANCETOLER: F; POWERRATING: 125m; NOMINALRESISTAN: 6.8; VAL2: 500mW,±1%; CDMASTERCADCELG: DR901A
R81 R85 = R: OriginalSymbolOrigin: (5080,5080); COMP: PRT_8; MAKER: KOA; VAL3: RK73B1JTTD102J; CHIPSIZE: 1608; VAL2: 125mW,±5%; PMPRODUCTSTYPEG: DME; MAXGCOUNT: 1; OUMEMAKER: KOA コーア; QUADMODEL: RES_1K; MOUNTINGFORMSMD: SMD; FNLEADFREETHET1GT2GMCTH1: N_N_N; OUMECLASSIFICATION: 表面実装用固定抵抗器; RESISTANCETOLER: J; POWERRATING: 100m; OUMEMAKERKATAMEI: RK73B1JRTTD102J; CDMASTERCADCELG: KCK0203; ADSMODELNAME: s_RK73B1JRTTD102J
R82 = R: OriginalSymbolOrigin: (5080,5080); COMP: PRT_8; MAKER: PANASONIC; VAL3: ERJ-3EKF1781V; CHIPSIZE: 1608; VAL2: 100mW,±1%; MAXGCOUNT: 1; OUMEMAKER: KOA コーア; QUADMODEL: RES_1.74K; MOUNTINGFORMSMD: SMD; FNLEADFREETHET1GT2GMCTH1: N_N_N; OUMECLASSIFICATION: 表面実装用固定抵抗器; RESISTANCETOLER: F; POWERRATING: 63m; OUMEMAKERKATAMEI: RK73H1JTD1741F; NOMINALRESISTAN: 1.74K; CDMASTERCADCELG: KC0008; ADSMODELNAME: s_RK73H1JTD1741F
R83 R87 = R: OriginalSymbolOrigin: (5080,5080); COMP: PRT_8; MAKER: PANASONIC; VAL3: ERJ-3EKF3571V; CHIPSIZE: 1608; VAL2: 100mW,±1%; MAXGCOUNT: 1; OUMEMAKER: NAE パナソニックエレクトロニックデバイス; QUADMODEL: RES_3.6K; MOUNTINGFORMSMD: SMD; FNLEADFREETHET1GT2GMCTH1: 3_1_N; OUMECLASSIFICATION: 表面実装用固定抵抗器; RESISTANCETOLER: F; POWERRATING: 63m; OUMEMAKERKATAMEI: ERJ3GEYF362V; NOMINALRESISTAN: 3.6K; CDMASTERCADCELG: DR802R; ADSMODELNAME: s_ERJ3GEYF362V
R86 = R: SQ_PART_MODEL: RES_1.74K; OriginalSymbolOrigin: (5080,5080); COMP: PRT_8; MAKER: PANASONIC; VAL3: ERJ-3EKF1781V; CHIPSIZE: 1608; VAL2: 100mW,±1%; MAXGCOUNT: 1; OUMEMAKER: KOA コーア; MOUNTINGFORMSMD: SMD; FNLEADFREETHET1GT2GMCTH1: N_N_N; OUMECLASSIFICATION: 表面実装用固定抵抗器; RESISTANCETOLER: F; ADSCNVFLAG: ON; POWERRATING: 63m; OUMEMAKERKATAMEI: RK73H1JTD1741F; ADSCOMPONENTNAME: R_1608; NOMINALRESISTAN: 1.74K; CDMASTERCADCELG: KC0008; ADSMODELNAME: s_RK73H1JTD1741F
R121 = R: OriginalSymbolOrigin: (5080,5080); COMP: PRT_8; VAL3: ERJ-3GEYJ1R0V; MAKER: PANASONIC; CHIPSIZE: 1608; VAL2: 100mW,±5%; MOUNTINGFORMSMD: SMD; OUMEMAKER: NAE パナソニックエレクトロニックデバイス; OUMEMAKERKATAMEI: ERJ3GEYJ1R0V; ADSMODELNAME: s_ERJ3GEYJ1R0V; PMPRODUCTSTYPEG: PC1; QUADMODEL: RES_1; FNLEADFREETHET1GT2GMCTH1: 2_1_N; OUMECLASSIFICATION: 表面実装用固定抵抗器; RESISTANCETOLER: J; POWERRATING: 63m; CDMASTERCADCELG: KC0008
R172 R173 = R: OriginalSymbolOrigin: (5080,5080); VAL3: RK73B1JTTD101J; MAKER: KOA; CHIPSIZE: 1608; VAL2: 125mW,±5%; COMP: PRT_8
T2 T3 = T2Q: OUMEPARTTYPE: T; OriginalSymbolOrigin: (5080,20320); COMP: PRT_7; MAKER: PONY; MAXGCOUNT: 1; OUMEMAKER: TDK ＴＤＫ; MAXRATEDCURREN1: 0; MOUNTINGFORMSMD: DIP; MAINOUTPUTVOLTA: 99.999K; FNLEADFREETHET1GT2GMCTH1: N_N_N; OUMECLASSIFICATION: 電源トランス; OUMEMAKERKATAMEI: CT332920S-46; CDMASTERCADCELG: DT0334; ADSMODELNAME: s_CT332920S_46
TP1-TP4 TP44 = TP: TIME: 16:12:21; UPDATEUSER: fukuda-y; UPDATETIME: 16:18:11; SAVECOUNT: 2; SAVEAREA0: -242,-92,12810,7836; OriginalSymbolOrigin: (0,7620); COMP: PRT_44; MAKER: MAC8
U?#2 = WAKU_DEF100: PLOTTIME: HH:MM; SAVEAREA0: -45080,-4508,463680,304612; TIME: 10:19:22; UPDATEUSER: f1043010; UPDATETIME: 13:49:57; SAVECOUNT: 3; OriginalSymbolOrigin: (10160,284480); PAGENUMBER: 2; DESIGNED: TOSHIBA

## Sheet 3.SchDoc
size 420 x 297 mm
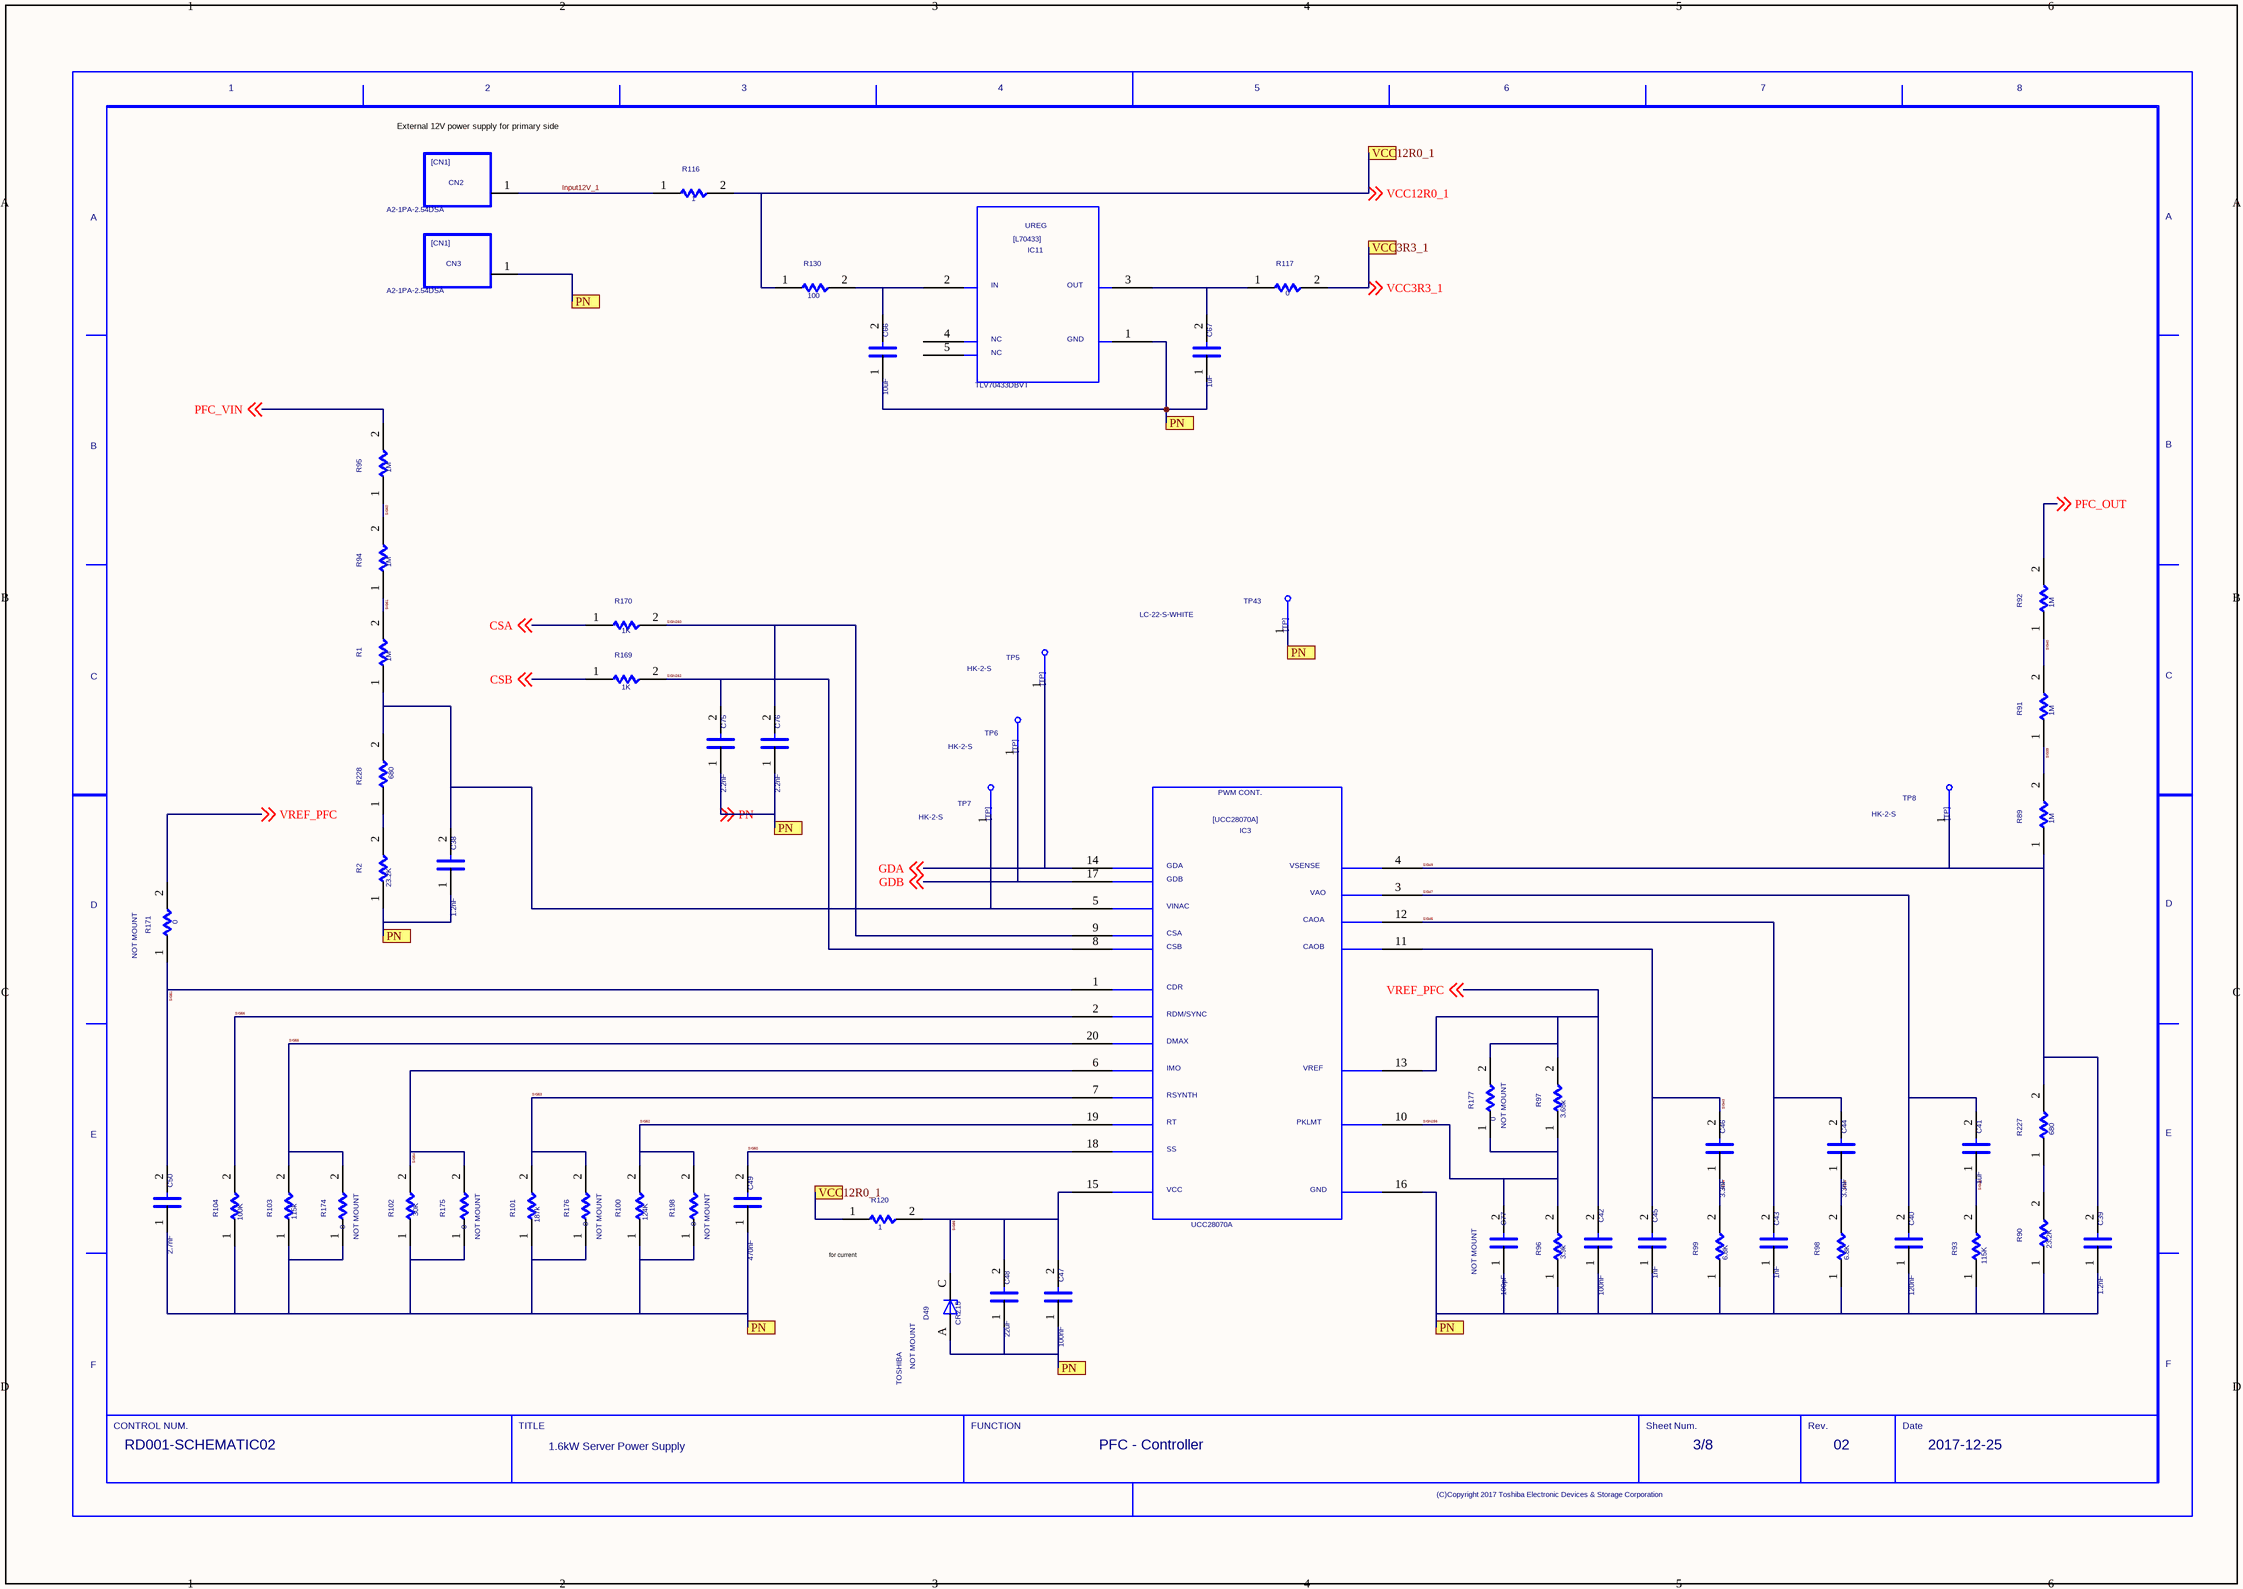
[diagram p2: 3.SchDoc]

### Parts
(Parts that share a designator on the sheet are numbered #1, #2 ... from top to bottom, then left to right.)
C38  VAL1: 1.2nF  (hidden comment: C)
C39  VAL1: 1.2nF  (hidden comment: C)
C40  VAL1: 120nF  (hidden comment: C)
C41  VAL1: 1uF  (hidden comment: C)
C42  VAL1: 100nF  (hidden comment: C)
C43  VAL1: 1nF  (hidden comment: C)
C44  VAL1: 3.3nF  (hidden comment: C)
C45  VAL1: 1nF  (hidden comment: C)
C46  VAL1: 3.3nF  (hidden comment: C)
C47  VAL1: 100nF  (hidden comment: C)
C48  VAL1: 22uF  (hidden comment: C)
C49  VAL1: 470nF  (hidden comment: C)
C50  VAL1: 2.7nF  (hidden comment: C)
C66  VAL1: 10uF  (hidden comment: C)
C67  VAL1: 1uF  (hidden comment: C)
C75  VAL1: 2.2nF  (hidden comment: C)
C76  VAL1: 2.2nF  (hidden comment: C)
C77  VAL1: 100pF  NOTMOUNT: NOT MOUNT  (hidden comment: C)
CN2  VAL3: A2-1PA-2.54DSA  (hidden comment: CN1)
CN3  VAL3: A2-1PA-2.54DSA  (hidden comment: CN1)
D49  USERCOMPTEXT3: TOSHIBA  NOTMOUNT: NOT MOUNT  VAL1: CRZ15  (hidden comment: ZD)
IC3  VAL3: UCC28070A  (hidden comment: L28070)
IC11  VAL3: TLV70433DBVT  (hidden comment: L70433)
R1  VAL1: 1M  (hidden comment: R)
R2  VAL1: 23.2K  (hidden comment: R)
R89  VAL1: 1M  (hidden comment: R)
R90  VAL1: 23.2K  (hidden comment: R)
R91  VAL1: 1M  (hidden comment: R)
R92  VAL1: 1M  (hidden comment: R)
R93  VAL1: 115K  (hidden comment: R)
R94  VAL1: 1M  (hidden comment: R)
R95  VAL1: 1M  (hidden comment: R)
R96  VAL1: 3.9k  (hidden comment: R)
R97  VAL1: 3.65k  (hidden comment: R)
R98  VAL1: 6.8K  (hidden comment: R)
R99  VAL1: 6.8K  (hidden comment: R)
R100  VAL1: 124K  (hidden comment: R)
R101  VAL1: 187k  (hidden comment: R)
R102  VAL1: 30K  (hidden comment: R)
R103  VAL1: 115k  (hidden comment: R)
R104  VAL1: 100K  (hidden comment: R)
R116  VAL1: 1  (hidden comment: R)
R117  VAL1: 0  (hidden comment: R)
R120  VAL1: 1  (hidden comment: R)
R130  VAL1: 100  (hidden comment: R)
R169  VAL1: 1K  (hidden comment: R)
R170  VAL1: 1K  (hidden comment: R)
R171  NOTMOUNT: NOT MOUNT  VAL1: 0  (hidden comment: R)
R174  VAL1: 0  NOTMOUNT: NOT MOUNT  (hidden comment: R)
R175  VAL1: 0  NOTMOUNT: NOT MOUNT  (hidden comment: R)
R176  VAL1: 0  NOTMOUNT: NOT MOUNT  (hidden comment: R)
R177  VAL1: 0  NOTMOUNT: NOT MOUNT  (hidden comment: R)
R198  VAL1: 0  NOTMOUNT: NOT MOUNT  (hidden comment: R)
R227  VAL1: 680  (hidden comment: R)
R228  VAL1: 680  (hidden comment: R)
TP5  VAL3: HK-2-S  (hidden comment: TP)
TP6  VAL3: HK-2-S  (hidden comment: TP)
TP7  VAL3: HK-2-S  (hidden comment: TP)
TP8  VAL3: HK-2-S  (hidden comment: TP)
TP43  VAL3: LC-22-S-WHITE  (hidden comment: TP)
U?#3  DATE: 2017-12-25  TITLE: 1.6kW Server Power Supply  REVISION: 02  SHEETNUMBER: 3/8  DRAWINGNUMBER: RD001-SCHEMATIC02  FUNCTION: PFC - Controller  (hidden comment: WAKU_DEF100)

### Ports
PN, VCC3R3_1, VCC12R0_1

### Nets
$BN000001: R90.2 R227.1
$BN000002: R2.2 R228.1
CSA: R170.1 ; off-sheet CSA
CSB: R169.1 ; off-sheet CSB
GDA: IC3.14 TP5.1 ; off-sheet GDA
GDB: IC3.17 TP6.1 ; off-sheet GDB
Input12V_1: CN2.1 R116.1
PFC_OUT: R92.2 ; off-sheet PFC_OUT
PFC_VIN: R95.2 ; off-sheet PFC_VIN
PN: C38.1 C39.1 C40.1 C42.1 C43.1 C45.1 C47.1 C48.1 C49.1 C50.1 C66.1 C67.1 C75.1 C76.1 C77.1 CN3.1 D49.A IC3.16 IC11.1 R2.1 R90.1 R93.1 R96.1 R98.1 R99.1 R100.1 R101.1 R102.1 R103.1 R104.1 R174.1 R175.1 R176.1 R198.1 TP43.1 ; off-sheet PN, port PN  [project net SIGN347]
SIG39: R89.2 R91.1
SIG40: R91.2 R92.1
SIG43: C45.2 C46.2 IC3.11
SIG44: C46.1 R99.2
SIG45: C43.2 C44.2 IC3.12
SIG46: C44.1 R98.2
SIG47: C40.2 C41.2 IC3.3
SIG48: C41.1 R93.2
SIG49: C39.2 IC3.4 R89.1 R227.2 TP8.1
SIG50: C49.2 IC3.18
SIG51: C50.2 IC3.1 R171.1
SIG52: IC3.19 R100.2 R198.2
SIG53: IC3.7 R101.2 R176.2
SIG54: IC3.6 R102.2 R175.2
SIG55: IC3.20 R103.2 R174.2
SIG56: IC3.2 R104.2
SIG60: R94.2 R95.1
SIG61: R1.2 R94.1
SIG62: C38.2 IC3.5 R1.1 R228.2 TP7.1
SIG86: C47.2 C48.2 D49.C IC3.15 R120.2
SIG185: C67.2 IC11.3 R117.1
SIG223: C66.2 IC11.2 R130.2
SIGN256: C77.2 IC3.10 R96.2 R97.1 R177.1
SIGN260: C76.2 IC3.9 R170.2
SIGN262: C75.2 IC3.8 R169.2
VCC3R3_1: R117.2 ; off-sheet VCC3R3_1, port VCC3R3_1
VCC12R0_1: R116.2 R120.1 R130.1 ; off-sheet VCC12R0_1, port VCC12R0_1
VREF_PFC: C42.2 IC3.13 R97.2 R171.2 R177.2 ; off-sheet VREF_PFC

Not connected (* = marked no-connect by the designer): IC11 4 5

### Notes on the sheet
- External 12V power supply for primary side
- for current
  measurement

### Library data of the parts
C38 C39 = C: OriginalSymbolOrigin: (2540,7620); COMP: PRT_52; VAL3: UMK105BJ122KV-F; MAKER: TDK; CHIPSIZE: 1005; VAL2: 50V,±10%; TEMPCHARACTERI2: B; PMPRODUCTSTYPEG: HD1; RATEDVOLTAGE: 50; MAXGCOUNT: 1; OUMEMAKER: TYD 太陽誘電; QUADMODEL: CON_1.2N; FNLEADFREETHET1GT2GMCTH1: 2_0_N; OUMECLASSIFICATION: セラミックコンデンサ; NOMINALCAPACITA: 1.2n; CAPACITANCETOLE: K; CDMASTERCADCELG: KC0005; ADSMODELNAME: s_UMK105BJ122KV_F
C40 = C: OriginalSymbolOrigin: (2540,7620); COMP: PRT_48; VAL3: GRM188R71E124KA01D; MAKER: MURATA; CHIPSIZE: 1608; VAL2: 25V,±10%; RATEDVOLTAGE: 25; MAXGCOUNT: 1; OUMEMAKER: MRT 村田製作所; QUADMODEL: CON_150N; FNLEADFREETHET1GT2GMCTH1: N_N_N; OUMECLASSIFICATION: セラミックコンデンサ; NOMINALCAPACITA: 150n; PMPRODUCTSTYPEG: DME; OUMEMAKERKATAMEI: GCM188R71E154KA37D; CAPACITANCETOLE: K; CDMASTERCADCELG: KC0008; ADSMODELNAME: s_GCM188R71E154KA37D
C41 = C: OriginalSymbolOrigin: (2540,7620); COMP: PRT_32; VAL3: C2012X7R1E105K125AB; MAKER: TDK; CHIPSIZE: 2012; VAL2: 25V,±10%; RATEDVOLTAGE: 50; MAXGCOUNT: 1; NOMINALCAPACITA: 1.5u; PMPRODUCTSTYPEG: DME; CAPACITANCETOLE: K; ADSMODELNAME: s_GCM31CR71H155KA55L
C42 = C: OriginalSymbolOrigin: (2540,7620); COMP: PRT_52; VAL3: C1005X7R1E104K050BB; MAKER: TDK; CHIPSIZE: 1005; VAL2: 25V,±10%; RATEDVOLTAGE: 25; MAXGCOUNT: 1; OUMEMAKER: MRT 村田製作所; QUADMODEL: CON_100N; FNLEADFREETHET1GT2GMCTH1: N_N_N; OUMECLASSIFICATION: セラミックコンデンサ; NOMINALCAPACITA: 100n; OUMEMAKERKATAMEI: GRM155R71E104KE14D; CAPACITANCETOLE: K; CDMASTERCADCELG: KC0005; ADSMODELNAME: s_GRM155R71E104KE14D
C43 C45 = C: OriginalSymbolOrigin: (2540,7620); COMP: PRT_52; PMPRODUCTSTYPEG: HD1-PC1; VAL3: UMK105BJ102KV-F; MAKER: TDK; CHIPSIZE: 1005; VAL2: 50V,±10%; RATEDVOLTAGE: 50; MAXGCOUNT: 1; TEMPCHARACTERI2: B; OUMEMAKER: TYD 太陽誘電; QUADMODEL: CON_1N; FNLEADFREETHET1GT2GMCTH1: 2_0_N; OUMECLASSIFICATION: セラミックコンデンサ; NOMINALCAPACITA: 1n; CAPACITANCETOLE: K; CDMASTERCADCELG: KC0005; ADSMODELNAME: s_UMK105BJ102KV_F
C44 C46 = C: OriginalSymbolOrigin: (2540,7620); COMP: PRT_52; VAL3: CGJ2B2X7R1E332K050BA; MAKER: TDK; CHIPSIZE: 1005; VAL2: 25V,±10%; RATEDVOLTAGE: 25; MAXGCOUNT: 1; OUMEMAKER: TDK ＴＤＫ; QUADMODEL: CON_3.3N; FNLEADFREETHET1GT2GMCTH1: N_N_N; OUMECLASSIFICATION: セラミックコンデンサ; NOMINALCAPACITA: 3.3n; OUMEMAKERKATAMEI: C1005JB1E332KT; CAPACITANCETOLE: K; CDMASTERCADCELG: KC0005; ADSMODELNAME: s_C1005JB1E332KT
C47 = C: SQ_PART_MODEL: CON_100N; OriginalSymbolOrigin: (2540,7620); COMP: PRT_52; VAL3: C1005X7R1E104K050BB; MAKER: TDK; CHIPSIZE: 1005; VAL2: 25V,±10%; RATEDVOLTAGE: 25; MAXGCOUNT: 1; OUMEMAKER: MRT 村田製作所; FNLEADFREETHET1GT2GMCTH1: N_N_N; OUMECLASSIFICATION: セラミックコンデンサ; NOMINALCAPACITA: 100n; ADSCNVFLAG: ON; OUMEMAKERKATAMEI: GRM155R71E104KE14D; ADSCOMPONENTNAME: C_1005; CAPACITANCETOLE: K; CDMASTERCADCELG: KC0005; ADSMODELNAME: s_GRM155R71E104KE14D
C48 = C: OriginalSymbolOrigin: (2540,7620); TEMPCHARACTERI2: B; COMP: PRT_51; VAL3: GRM31CR61E226KE15L; MAKER: MURATA; CHIPSIZE: 3216; VAL2: 25V,±10%; RATEDVOLTAGE: 25; MAXGCOUNT: 1; OUMEMAKER: MRT 村田製作所; QUADMODEL: CON_22U; FNLEADFREETHET1GT2GMCTH1: N_N_N; OUMECLASSIFICATION: セラミックコンデンサ; NOMINALCAPACITA: 22u; OUMEMAKERKATAMEI: GRM31CB31E226ME15D; CAPACITANCETOLE: M; CDMASTERCADCELG: KC0014; ADSMODELNAME: s_GRM31CB31E226ME15D
C49 = C: OriginalSymbolOrigin: (2540,7620); COMP: PRT_52; VAL3: C1005X5R1E474K050BB; MAKER: TDK; CHIPSIZE: 1005; VAL2: 25V,±10%; RATEDVOLTAGE: 25; MAXGCOUNT: 1; OUMEMAKER: MRT 村田製作所; QUADMODEL: CON_100N; FNLEADFREETHET1GT2GMCTH1: N_N_N; OUMECLASSIFICATION: セラミックコンデンサ; NOMINALCAPACITA: 100n; OUMEMAKERKATAMEI: GRM155R71E104KE14D; CAPACITANCETOLE: K; CDMASTERCADCELG: KC0005; ADSMODELNAME: s_GRM155R71E104KE14D
C50 = C: OriginalSymbolOrigin: (2540,7620); COMP: PRT_52; VAL3: UMK105BJ272KV-F; MAKER: TDK; CHIPSIZE: 1005; VAL2: 50V,±10%; RATEDVOLTAGE: 50; MAXGCOUNT: 1; TEMPCHARACTERI2: B; OUMEMAKER: TYD 太陽誘電; QUADMODEL: CON_2.7N; FNLEADFREETHET1GT2GMCTH1: 3_0_N; OUMECLASSIFICATION: セラミックコンデンサ; NOMINALCAPACITA: 2.7n; PMPRODUCTSTYPEG: PC1; CAPACITANCETOLE: K; CDMASTERCADCELG: DC834K; ADSMODELNAME: s_UMK105BJ272KV_F
C66 = C: OriginalSymbolOrigin: (2540,7620); COMP: PRT_48; VAL3: C1608X5R1E106M080AC; MAKER: TDK; CHIPSIZE: 1608; VAL2: 25V,±20%; RATEDVOLTAGE: 25; MAXGCOUNT: 1; OUMEMAKER: MRT 村田製作所; QUADMODEL: CON_10U; FNLEADFREETHET1GT2GMCTH1: N_N_N; OUMECLASSIFICATION: セラミックコンデンサ; NOMINALCAPACITA: 10u; OUMEMAKERKATAMEI: ZRB18AR61E106ME01L; CAPACITANCETOLE: M; CDMASTERCADCELG: KC0167; ADSMODELNAME: s_ZRB18AR61E106ME01L
C67 = C: SQ_PART_MODEL: CON_1U; OriginalSymbolOrigin: (2540,7620); COMP: PRT_52; VAL3: C1005X5R1E105M050BC; MAKER: TDK; CHIPSIZE: 1005; VAL2: 25V,±20%; RATEDVOLTAGE: 25; MAXGCOUNT: 1; TEMPCHARACTERI2: B; OUMEMAKER: MRT 村田製作所; FNLEADFREETHET1GT2GMCTH1: N_N_N; OUMECLASSIFICATION: セラミックコンデンサ; SIZECODESMD: 1608; NOMINALCAPACITA: 1u; PMPRODUCTSTYPEG: HD1; ADSCNVFLAG: ON; OUMEMAKERKATAMEI: GRM185B31E105KA12D; ADSCOMPONENTNAME: C_1608; CAPACITANCETOLE: K; CDMASTERCADCELG: KC0008; ADSMODELNAME: s_GRM185B31E105KA12D
C75 = C: OriginalSymbolOrigin: (2540,7620); COMP: PRT_52; VAL3: UMK105BJ222KV-F; MAKER: TDK; CHIPSIZE: 1005; VAL2: 50V,±10%; RATEDVOLTAGE: 50; MAXGCOUNT: 1; TEMPCHARACTERI2: B; OUMEMAKER: TYD 太陽誘電; QUADMODEL: CON_2.2N; FNLEADFREETHET1GT2GMCTH1: 2_0_N; OUMECLASSIFICATION: セラミックコンデンサ; NOMINALCAPACITA: 2.2n; PMPRODUCTSTYPEG: HD1-PC1; CAPACITANCETOLE: K; CDMASTERCADCELG: KC0005; ADSMODELNAME: s_UMK105BJ222KV_F
C76 = C: OriginalSymbolOrigin: (2540,7620); COMP: PRT_52; VAL3: UMK105BJ222KV-F; MAKER: TDK; CHIPSIZE: 1005; VAL2: 50V,±10%; OLDCOMPONENTID: 99; RATEDVOLTAGE: 50; MAXGCOUNT: 1; TEMPCHARACTERI2: B; OUMEMAKER: TYD 太陽誘電; QUADMODEL: CON_2.2N; FNLEADFREETHET1GT2GMCTH1: 2_0_N; OUMECLASSIFICATION: セラミックコンデンサ; NOMINALCAPACITA: 2.2n; PMPRODUCTSTYPEG: HD1-PC1; CAPACITANCETOLE: K; CDMASTERCADCELG: KC0005; ADSMODELNAME: s_UMK105BJ222KV_F
C77 = C: OriginalSymbolOrigin: (2540,7620); VAL3: GRM1885C1H101JA01D; VAL2: 50V,±5%; MAKER: MURATA; CHIPSIZE: 1608; COMP: PRT_48
CN2 CN3 = CN1: OriginalSymbolOrigin: (2540,12700); VAL2: 200V; VAL1: 3A; MAKER: HIROSE; COMP: PRT_57; UPDATETIME: 10:27:25; UPDATEUSER: s.maruyama; TIME: 13:28:28; SAVECOUNT: 26; SAVEAREA0: -4590,-655,24652,18633
D49 = ZD: OUMEPARTTYPE: D; SAVEAREA0: -4630,-153,17114,13055; TIME: 14:49:55; UPDATEUSER: fukuda-y; UPDATETIME: 08:18:42; SAVECOUNT: 6; OriginalSymbolOrigin: (5080,5080); COMP: PRT_6; FORWARDVOLTAGEM: 0; MAXGCOUNT: 1; OUMEMAKER: TSB 東芝; MOUNTINGFORMSMD: SMD; FNLEADFREETHET1GT2GMCTH1: N_N_N; ZENERVOLTAGEMIN: 13.5; OUMECLASSIFICATION: 定電圧ダイオード; CDMASTERCADCELG: MMK0167; ZENERVOLTAGEMAX: 16.5; ADSMODELNAME: s_CRZ15
IC3 = L28070: SAVEAREA0: -12344,-1037,78634,87348; SAVECOUNT: 29; TIME: 15:02:55; UPDATEUSER: cae; UPDATETIME: 14:36:12; OriginalSymbolOrigin: (7620,83820); MAKER: TEXAS; COMP: PRT_59
IC11 = L70433: SAVEAREA0: -444,-3509,43701,41525; TIME: 18:31:00; UPDATEUSER: cae; UPDATETIME: 13:31:05; SAVECOUNT: 12; OriginalSymbolOrigin: (7620,35560); MAKER: TEXAS; COMP: PRT_10
R1 R91 R92 R94 R95 = R: OriginalSymbolOrigin: (5080,5080); COMP: PRT_8; MAKER: KOA; VAL3: RK73B1JTTD105J; CHIPSIZE: 1608; VAL2: 100mW,±5%; MAXGCOUNT: 1; OUMEMAKER: KOA コーア; QUADMODEL: RES_1M; MOUNTINGFORMSMD: SMD; FNLEADFREETHET1GT2GMCTH1: N_N_N; OUMECLASSIFICATION: 表面実装用固定抵抗器; RESISTANCETOLER: F; POWERRATING: 100m; OUMEMAKERKATAMEI: RK73H1JTTD1004F; CDMASTERCADCELG: KC0167; ADSMODELNAME: s_RK73H1JTTD1004F
R2 = R: OriginalSymbolOrigin: (5080,5080); COMP: PRT_8; MAKER: PANASONIC; VAL3: ERJ-3EKF2322V; CHIPSIZE: 1608; VAL2: 100mW,±1%; MOUNTINGFORMSMD: SMD; OUMEMAKER: NAE パナソニックエレクトロニックデバイス; OUMEMAKERKATAMEI: ERJ3GEYJ243V; ADSMODELNAME: s_ERJ3GEYJ243V; MAXGCOUNT: 1; QUADMODEL: RES_24K; FNLEADFREETHET1GT2GMCTH1: 3_1_N; OUMECLASSIFICATION: 表面実装用固定抵抗器; RESISTANCETOLER: J; POWERRATING: 63m; NOMINALRESISTAN: 24K; CDMASTERCADCELG: KC0008
R89 = R: OriginalSymbolOrigin: (5080,5080); COMP: PRT_8; MAKER: KOA; VAL3: RK73B1JTTD105J; CHIPSIZE: 1608; VAL2: 100mW; MAXGCOUNT: 1; OUMEMAKER: KOA コーア; QUADMODEL: RES_1M; MOUNTINGFORMSMD: SMD; FNLEADFREETHET1GT2GMCTH1: N_N_N; OUMECLASSIFICATION: 表面実装用固定抵抗器; RESISTANCETOLER: F; POWERRATING: 100m; OUMEMAKERKATAMEI: RK73H1JTTD1004F; CDMASTERCADCELG: KC0167; ADSMODELNAME: s_RK73H1JTTD1004F
R90 = R: OriginalSymbolOrigin: (5080,5080); COMP: PRT_8; MAKER: PANASONIC; VAL3: ERJ-3EKF2322V; CHIPSIZE: 1608; VAL2: 100mW,±1%; MAXGCOUNT: 1; OUMEMAKER: NAE パナソニックエレクトロニックデバイス; QUADMODEL: RES_22K; MOUNTINGFORMSMD: SMD; FNLEADFREETHET1GT2GMCTH1: N_N_N; OUMECLASSIFICATION: 表面実装用固定抵抗器; RESISTANCETOLER: F; POWERRATING: 100m; OUMEMAKERKATAMEI: ERJ3EKF2202V; NOMINALRESISTAN: 22K; CDMASTERCADCELG: KC0008; ADSMODELNAME: s_ERJ3EKF2202V
R93 = R: OriginalSymbolOrigin: (5080,5080); COMP: PRT_8; MAKER: PANASONIC; VAL3: ERJ-3EKF1153V; CHIPSIZE: 1608; VAL2: 100mW,±1%; MAXGCOUNT: 1; OUMEMAKER: NAE パナソニックエレクトロニックデバイス; QUADMODEL: RES_110K; MOUNTINGFORMSMD: SMD; FNLEADFREETHET1GT2GMCTH1: N_N_N; OUMECLASSIFICATION: 表面実装用固定抵抗器; RESISTANCETOLER: F; POWERRATING: 100m; OUMEMAKERKATAMEI: ERJ3EKF1103V; NOMINALRESISTAN: 110K; CDMASTERCADCELG: KC0008; ADSMODELNAME: s_ERJ3EKF1103V
R96 = R: OriginalSymbolOrigin: (5080,5080); COMP: PRT_8; VAL3: RK73B1JTTD392J; MAKER: KOA; CHIPSIZE: 1608; VAL2: 100mW,±5%
R97 = R: OriginalSymbolOrigin: (5080,5080); COMP: PRT_8; VAL3: ERJ-3EKF3651V; MAKER: PANASONIC; CHIPSIZE: 1608; VAL2: 100mW,±1%
R98 R99 = R: OriginalSymbolOrigin: (5080,5080); COMP: PRT_8; VAL3: RK73B1JTTD682J; MAKER: KOA; CHIPSIZE: 1608; VAL2: 100mW,±5%; MAXGCOUNT: 1; OUMEMAKER: KOA コーア; QUADMODEL: RES_6.8K; MOUNTINGFORMSMD: SMD; FNLEADFREETHET1GT2GMCTH1: N_N_N; OUMECLASSIFICATION: 表面実装用固定抵抗器; RESISTANCETOLER: B; PMPRODUCTSTYPEG: DME; POWERRATING: 100m; OUMEMAKERKATAMEI: RN73H1JTTD6801B10; CDMASTERCADCELG: KCK0203; ADSMODELNAME: s_RN73H1JTTD6801B10
R100 = R: OriginalSymbolOrigin: (5080,5080); COMP: PRT_8; VAL3: ERJ-3EKF1243V; MAKER: PANASONIC; CHIPSIZE: 1608; VAL2: 100mW,±1%; MAXGCOUNT: 1; OUMEMAKER: NAE パナソニックエレクトロニックデバイス; QUADMODEL: RES_120K; MOUNTINGFORMSMD: SMD; FNLEADFREETHET1GT2GMCTH1: N_N_N; OUMECLASSIFICATION: 表面実装用固定抵抗器; RESISTANCETOLER: F; POWERRATING: 100m; OUMEMAKERKATAMEI: ERJ3EKF1203V; NOMINALRESISTAN: 120K; CDMASTERCADCELG: KC0008; ADSMODELNAME: s_ERJ3EKF1203V
R101 = R: OriginalSymbolOrigin: (5080,5080); COMP: PRT_8; VAL3: ERJ-3EKF1873V; MAKER: PANASONIC; CHIPSIZE: 1608; VAL2: 100mW,±1%
R102 = R: OriginalSymbolOrigin: (5080,5080); COMP: PRT_8; VAL3: RK73H1JTTD3002F; MAKER: KOA; CHIPSIZE: 1608; VAL2: 100mW,±1%; MAXGCOUNT: 1; OUMEMAKER: KOA コーア; QUADMODEL: RES_30K; MOUNTINGFORMSMD: SMD; FNLEADFREETHET1GT2GMCTH1: N_N_N; OUMECLASSIFICATION: 表面実装用固定抵抗器; RESISTANCETOLER: B; POWERRATING: 100m; OUMEMAKERKATAMEI: RN73H1JTTD3002B10; CDMASTERCADCELG: KC0008; ADSMODELNAME: s_RN73H1JTTD3002B10
R103 = R: OriginalSymbolOrigin: (5080,5080); COMP: PRT_8; VAL3: ERJ-3EKF1153V; MAKER: PANASONIC; CHIPSIZE: 1608; VAL2: 100mW,±1%
R104 = R: OriginalSymbolOrigin: (5080,5080); COMP: PRT_8; VAL3: RK73B1JTTD104J; MAKER: KOA; CHIPSIZE: 1608; VAL2: 100mW,±5%; MAXGCOUNT: 1; OUMEMAKER: KOA コーア; QUADMODEL: RES_100K; MOUNTINGFORMSMD: SMD; FNLEADFREETHET1GT2GMCTH1: N_N_N; OUMECLASSIFICATION: 表面実装用固定抵抗器; RESISTANCETOLER: G; POWERRATING: 100m; OUMEMAKERKATAMEI: RK73B1JTTD104G; CDMASTERCADCELG: KC0008; ADSMODELNAME: s_RK73B1JTTD104G
R116 = R: OriginalSymbolOrigin: (5080,5080); COMP: PRT_8; VAL3: ERJ-3GEYJ1R0V; MAKER: PANASONIC; CHIPSIZE: 1608; VAL2: 100mW,±5%; PMPRODUCTSTYPEG: PC1; OUMEMAKER: NAE パナソニックエレクトロニックデバイス; QUADMODEL: RES_1; MOUNTINGFORMSMD: SMD; FNLEADFREETHET1GT2GMCTH1: 2_1_N; OUMECLASSIFICATION: 表面実装用固定抵抗器; RESISTANCETOLER: J; POWERRATING: 63m; OUMEMAKERKATAMEI: ERJ3GEYJ1R0V; CDMASTERCADCELG: KC0008; ADSMODELNAME: s_ERJ3GEYJ1R0V
R117 = R: SQ_PART_MODEL: RES_0; OriginalSymbolOrigin: (5080,5080); COMP: PRT_8; VAL3: RK73Z1JTTD; MAKER: KOA; CHIPSIZE: 1608; VAL2: 100mW; PMPRODUCTSTYPEG: HD1-PC1; MAXGCOUNT: 1; OUMEMAKER: NAE パナソニックエレクトロニックデバイス; MOUNTINGFORMSMD: SMD; FNLEADFREETHET1GT2GMCTH1: 2_1_N; OUMECLASSIFICATION: 表面実装用固定抵抗器; SIZECODESMD: 1005; RESISTANCETOLER: X; ADSCNVFLAG: ON; POWERRATING: 63m; OUMEMAKERKATAMEI: ERJ2GE0R00X; ADSCOMPONENTNAME: R_1005; CDMASTERCADCELG: KC0005; ADSMODELNAME: s_ERJ2GE0R00X
R120 = R: as R121 on sheet 2
R130 = R: OriginalSymbolOrigin: (5080,5080); COMP: PRT_8; VAL3: RK73B1JTTD101J; MAKER: KOA; CHIPSIZE: 1608; VAL2: 125mW,±5%; MAXGCOUNT: 1; OUMEMAKER: NAE パナソニックエレクトロニックデバイス; QUADMODEL: RES_100; MOUNTINGFORMSMD: SMD; FNLEADFREETHET1GT2GMCTH1: N_N_N; OUMECLASSIFICATION: 表面実装用固定抵抗器; RESISTANCETOLER: F; PMPRODUCTSTYPEG: DA; POWERRATING: 250m; OUMEMAKERKATAMEI: ERJPA3F1000V@@; CDMASTERCADCELG: KC0165; ADSMODELNAME: s_ERJPA3F1000V@@
R169 = R: OriginalSymbolOrigin: (5080,5080); PMPRODUCTSTYPEG: DME; COMP: PRT_8; VAL3: RK73B1JTTD102J; MAKER: KOA; CHIPSIZE: 1608; VAL2: 125mW,±5%; MAXGCOUNT: 1; OUMEMAKER: KOA コーア; QUADMODEL: RES_1K; MOUNTINGFORMSMD: SMD; FNLEADFREETHET1GT2GMCTH1: N_N_N; OUMECLASSIFICATION: 表面実装用固定抵抗器; RESISTANCETOLER: G; POWERRATING: 100m; OUMEMAKERKATAMEI: RK73B1JTTD102G; CDMASTERCADCELG: KCK0203; ADSMODELNAME: s_RK73B1JTTD102G
R170 = R: OriginalSymbolOrigin: (5080,5080); PMPRODUCTSTYPEG: DME; COMP: PRT_8; VAL3: RK73B1JTTD102J; MAKER: KOA; CHIPSIZE: 1608; VAL2: 125mW,±5%; OLDCOMPONENTID: 100; MAXGCOUNT: 1; OUMEMAKER: KOA コーア; QUADMODEL: RES_1K; MOUNTINGFORMSMD: SMD; FNLEADFREETHET1GT2GMCTH1: N_N_N; OUMECLASSIFICATION: 表面実装用固定抵抗器; RESISTANCETOLER: G; POWERRATING: 100m; OUMEMAKERKATAMEI: RK73B1JTTD102G; CDMASTERCADCELG: KCK0203; ADSMODELNAME: s_RK73B1JTTD102G
R171 = R: OriginalSymbolOrigin: (5080,5080); COMP: PRT_8; VAL3: RK73Z1JTTD; VAL2: 100mW; MAKER: KOA; CHIPSIZE: 1608; MAXGCOUNT: 1; OUMEMAKER: KOA コーア; QUADMODEL: RES_0; MOUNTINGFORMSMD: SMD; FNLEADFREETHET1GT2GMCTH1: 3_2_N; OUMECLASSIFICATION: 表面実装用固定抵抗器; RESISTANCETOLER: X; PMPRODUCTSTYPEG: DME-HD1-PC1; POWERRATING: 100m; CDMASTERCADCELG: KCK0203; ADSMODELNAME: s_RK73Z1JTTD
R174-R177 R198 = R: OriginalSymbolOrigin: (5080,5080); COMP: PRT_8; VAL3: RK73Z1JTTD; VAL2: 100mW; MAKER: KOA; CHIPSIZE: 1608
R227 R228 = R: OriginalSymbolOrigin: (5080,5080); COMP: PRT_8; VAL3: RK73H1JTTD6800F; MAKER: KOA; CHIPSIZE: 1608; VAL2: 100mW,±1%
TP5-TP8 = TP: as TP1 on sheet 2
TP43 = TP: as TP45 on sheet 1
U?#3 = WAKU_DEF100: PLOTTIME: HH:MM; SAVEAREA0: -45080,-4508,463680,304612; TIME: 14:20:16; UPDATEUSER: f1043010; UPDATETIME: 13:49:58; SAVECOUNT: 3; OriginalSymbolOrigin: (10160,284480); DESIGNED: TOSHIBA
